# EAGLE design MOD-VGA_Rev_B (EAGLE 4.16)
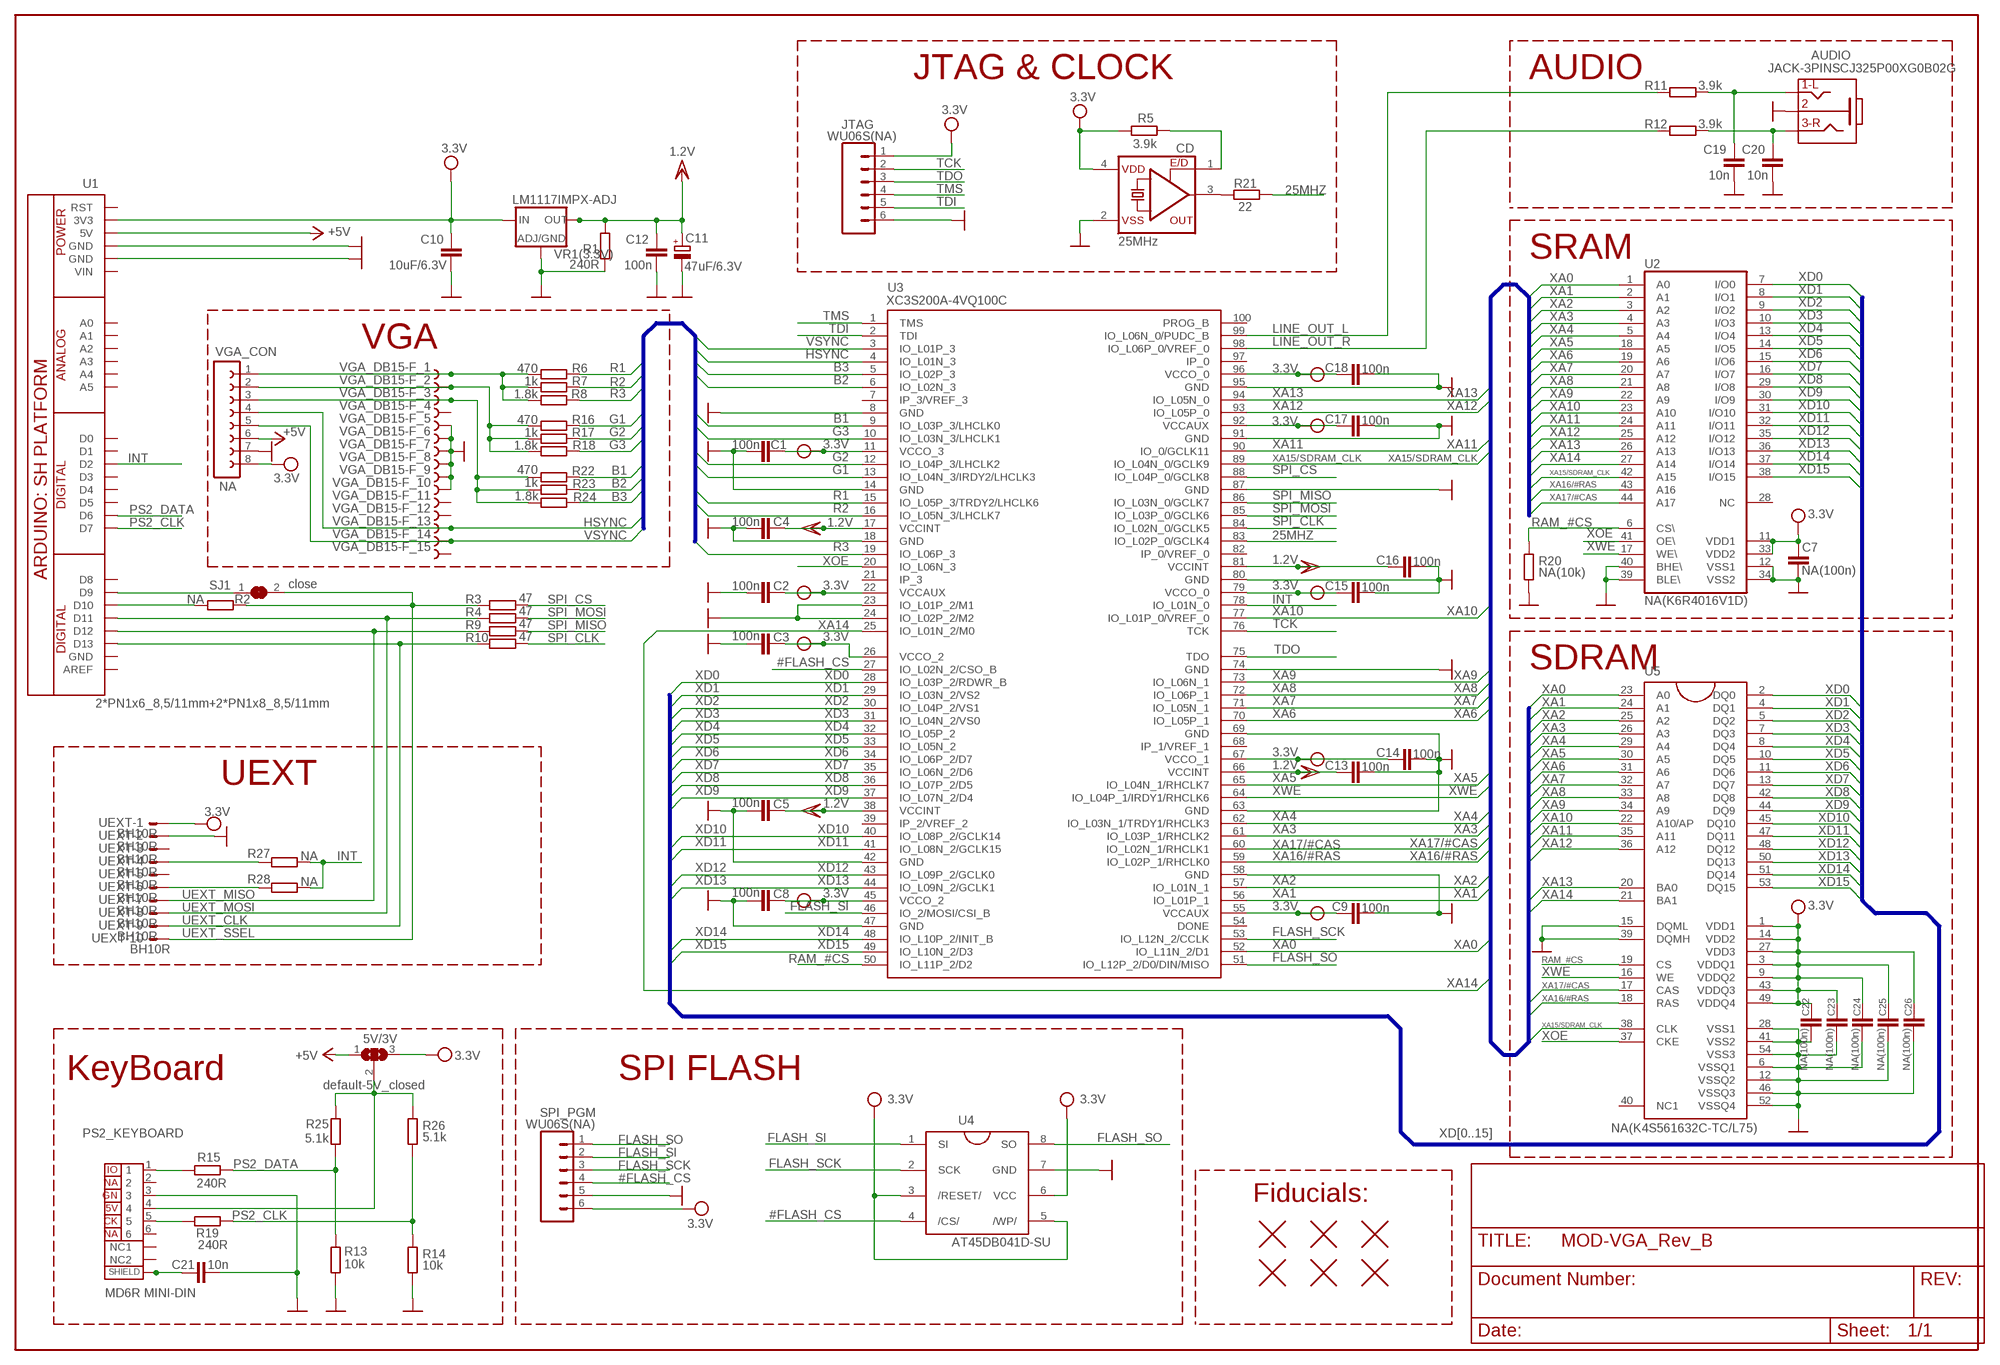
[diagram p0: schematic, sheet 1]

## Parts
5V/3V  default-5V_closed  SJ2W  [SJ_2]
AUDIO  JACK-3PINSCJ325P00XG0B02G  [PHONE_JACK-SMD]
C1  100n  C-EUC0603_5MIL  [C0603_5MIL]
C2  100n  C-EUC0603_5MIL  [C0603_5MIL]
C3  100n  C-EUC0603_5MIL  [C0603_5MIL]
C4  100n  C-EUC0603_5MIL  [C0603_5MIL]
C5  100n  C-EUC0603_5MIL  [C0603_5MIL]
C7  NA(100n)  C-EUC0603MM_NA  [C0603_MM_NA]
C8  100n  C-EUC0603_5MIL  [C0603_5MIL]
C9  100n  C-EUC0603_5MIL  [C0603_5MIL]
C10  10uF/6.3V  C-EUC0603_5MIL  [C0603_5MIL]
C11  47uF/6.3V  CPOL-EUCT3528  [CT3528]
C12  100n  C-EUC0603_5MIL  [C0603_5MIL]
C13  100n  C-EUC0603_5MIL  [C0603_5MIL]
C14  100n  C-EUC0603_5MIL  [C0603_5MIL]
C15  100n  C-EUC0603_5MIL  [C0603_5MIL]
C16  100n  C-EUC0603_5MIL  [C0603_5MIL]
C17  100n  C-EUC0603_5MIL  [C0603_5MIL]
C18  100n  C-EUC0603_5MIL  [C0603_5MIL]
C19  10n  C-EUC0603_5MIL  [C0603_5MIL]
C20  10n  C-EUC0603_5MIL  [C0603_5MIL]
C21  10n  C-EUC0603_5MIL  [C0603_5MIL]
C22  NA(100n)  C-EUC0603MM_NA  [C0603_MM_NA]
C23  NA(100n)  C-EUC0603MM_NA  [C0603_MM_NA]
C24  NA(100n)  C-EUC0603MM_NA  [C0603_MM_NA]
C25  NA(100n)  C-EUC0603MM_NA  [C0603_MM_NA]
C26  NA(100n)  C-EUC0603MM_NA  [C0603_MM_NA]
CD  25MHz  6NC2_CLOCK_DRIVER  [7X5MM_CLOCK_DRIVER]
FID1  FIDUCIAL1X2  [FIDUCIAL-1X2]
FID2  FIDUCIAL1X2  [FIDUCIAL-1X2]
FID3  FIDUCIAL1X2  [FIDUCIAL-1X2]
FID4  FIDUCIAL1X2  [FIDUCIAL-1X2]
FID5  FIDUCIAL1X2  [FIDUCIAL-1X2]
FID6  FIDUCIAL1X2  [FIDUCIAL-1X2]
JTAG  WU06S(NA)  CON61.27MM-6-SMALL  [CON1.27MM-6-SMALL_TRANSITIVE]
PS2_KEYBOARD  MD6R MINI-DIN  PS2PS2  [PS2]
R1  240R  R-EU_R0603_5MIL  [R0603_5MIL]
R2  NA  R-EU_NA  [R0603_NA]
R3  47  R-EU_R0603_5MIL  [R0603_5MIL]
R4  47  R-EU_R0603_5MIL  [R0603_5MIL]
R5  3.9k  R-EU_R0603_5MIL  [R0603_5MIL]
R6  470  R-EU_R0603_5MIL  [R0603_5MIL]
R7  1k  R-EU_R0603_5MIL  [R0603_5MIL]
R8  1.8k  R-EU_R0603_5MIL  [R0603_5MIL]
R9  47  R-EU_R0603_5MIL  [R0603_5MIL]
R10  47  R-EU_R0603_5MIL  [R0603_5MIL]
R11  3.9k  R-EU_R0603_5MIL  [R0603_5MIL]
R12  3.9k  R-EU_R0603_5MIL  [R0603_5MIL]
R13  10k  R-EU_R0603_5MIL  [R0603_5MIL]
R14  10k  R-EU_R0603_5MIL  [R0603_5MIL]
R15  240R  R-EU_R0603_5MIL  [R0603_5MIL]
R16  470  R-EU_R0603_5MIL  [R0603_5MIL]
R17  1k  R-EU_R0603_5MIL  [R0603_5MIL]
R18  1.8k  R-EU_R0603_5MIL  [R0603_5MIL]
R19  240R  R-EU_R0603_5MIL  [R0603_5MIL]
R20  NA(10k)  R-EU_R0603MM_NA  [R0603MM_NA]
R21  22  R-EU_R0603_5MIL  [R0603_5MIL]
R22  470  R-EU_R0603_5MIL  [R0603_5MIL]
R23  1k  R-EU_R0603_5MIL  [R0603_5MIL]
R24  1.8k  R-EU_R0603_5MIL  [R0603_5MIL]
R25  5.1k  R-EU_R0603_5MIL  [R0603_5MIL]
R26  5.1k  R-EU_R0603_5MIL  [R0603_5MIL]
R27  NA  R-EU_R0603_5MIL  [R0603_5MIL]
R28  NA  R-EU_R0603_5MIL  [R0603_5MIL]
SJ1  close  SJSJ-CLOSE  [SJ-CLOSE]
SPI_PGM  WU06S(NA)  CON61.27MM-6-SMALL  [CON1.27MM-6-SMALL_TRANSITIVE]
U1  2*PN1x6_8,5/11mm+2*PN1x8_8,5/11mm  ARDUINO_SH_PLATFORM2  [ARDUINO_MIDI_PLATFORM]
U2  NA(K6R4016V1D)  IDT71V416L  [44TSOP1]
U3  XC3S200A-4VQ100C  XC3S200A  [S-PQFP-G100]
U4  AT45DB041D-SU  AT45DB041B_1  [AT45DB041B_1]
U5  NA(K4S561632C-TC/L75)  K4S561632C-TC/L75  [54TSOPII]
UEXT  BH10R  ML10LE  [ML10L]
VGA_CON  NA  FE08-1  [FE08]
VGA_DB15-F  VGA15  DB1522  [DB15-F_22MM]
VR1(3.3V)  LM1117IMPX-ADJ  LM1117  [SOT223]

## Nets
25MHZ: R21.2 U3.83(IO_L02P_0/GCLK4)
#FLASH_CS: SPI_PGM.4 U3.27(IO_L02N_2/CSO_B) U4.4(/CS/)
+5V: 5V/3V.1 U1.5V VGA_CON.6
B1: R22.2 U3.9(IO_L03P_3/LHCLK0)
B2: R23.2 U3.6(IO_L02N_3)
B3: R24.1 U3.5(IO_L02P_3)
FLASH_SCK: SPI_PGM.3 U3.53(IO_L12N_2/CCLK) U4.2(SCK)
FLASH_SI: SPI_PGM.2 U3.46(IO_2/MOSI/CSI_B) U4.1(SI)
FLASH_SO: SPI_PGM.1 U3.51(IO_L12P_2/D0/DIN/MISO) U4.8(SO)
G1: R16.2 U3.13(IO_L04N_3/IRDY2/LHCLK3)
G2: R17.2 U3.12(IO_L04P_3/LHCLK2)
G3: R18.2 U3.10(IO_L03N_3/LHCLK1)
GND [pwr]: AUDIO.1 C1.2 C2.2 C3.2 C4.2 C5.2 C7.2 C8.2 C9.2 C10.2 C11.- C12.2 C13.2 C14.2 C15.2 C16.2 C17.2 C18.2 C19.2 C20.2 C21.2 C22.2 C23.2 C24.2 C25.2 C26.2 CD.2(VSS) JTAG.6 PS2_KEYBOARD.3 R1.2 R13.2 R14.2 R20.2 SPI_PGM.5 U1.GND U1.GND@1(GND) U2.12(VSS1) U2.34(VSS2) U2.39(BLE\) U2.40(BHE\) U3.8(GND) U3.14(GND) U3.18(GND) U3.23(IO_L01P_2/M1) U3.24(IO_L02P_2/M2) U3.42(GND) U3.47(GND) U3.58(GND) U3.63(GND) U3.69(GND) U3.74(GND) U3.80(GND) U3.87(GND) U3.91(GND) U3.95(GND) U4.7(GND) U5.6(VSSQ1) U5.12(VSSQ2) U5.15(DQML) U5.28(VSS1) U5.39(DQMH) U5.41(VSS2) U5.46(VSSQ3) U5.52(VSSQ4) U5.54(VSS3) UEXT.2 VGA_CON.7 VGA_DB15-F.5 VGA_DB15-F.6 VGA_DB15-F.7 VGA_DB15-F.8 VGA_DB15-F.9 VGA_DB15-F.10 VR1(3.3V).1(ADJ/GND)
HSYNC: U3.4(IO_L01N_3) VGA_CON.4 VGA_DB15-F.13
INT: R27.2 R28.2 U1.D2 U3.78(IO_L01N_0)
LINE_OUT_L: R11.2 U3.99(IO_L06N_0/PUDC_B)
LINE_OUT_R: R12.2 U3.98(IO_L06P_0/VREF_0)
N$1: R2.1 U1.D10
N$2: SJ1.1 U1.D9
N$3: PS2_KEYBOARD.1 R15.1
N$4: PS2_KEYBOARD.5 R19.1
N$5: 5V/3V.2 PS2_KEYBOARD.4 R25.1 R26.1
N$6: CD.1(E/D) R5.1
N$7: R27.1 UEXT.4
N$9: AUDIO.5 C19.1 R11.1
N$10: AUDIO.2 C20.1 R12.1
N$11: CD.3(OUT) R21.1
N$12: R28.1 UEXT.6
N$29: R16.1 R17.1 R18.1 VGA_CON.2 VGA_DB15-F.2
N$37: R6.1 R7.1 R8.1 VGA_CON.1 VGA_DB15-F.1
N$40: R22.1 R23.1 R24.2 VGA_CON.3 VGA_DB15-F.3
N$86: C21.1 PS2_KEYBOARD.SHIELD1 PS2_KEYBOARD.SHIELD2 PS2_KEYBOARD.SHIELD3
PS2_CLK: R14.1 R19.2 R26.2 U1.D7
PS2_DATA: R13.1 R15.2 R25.2 U1.D6
R1: R6.2 U3.15(IO_L05P_3/TRDY2/LHCLK6)
R2: R7.2 U3.16(IO_L05N_3/LHCLK7)
R3: R8.2 U3.19(IO_L06P_3)
RAM_#CS: R20.1 U2.6(CS\) U3.50(IO_L11P_2/D2) U5.19(CS)
SPI_CLK: R10.2 U3.84(IO_L02N_0/GCLK5)
SPI_CS: R3.2 U3.88(IO_L04P_0/GCLK8)
SPI_MISO: R9.2 U3.86(IO_L03N_0/GCLK7)
SPI_MOSI: R4.2 U3.85(IO_L03P_0/GCLK6)
TCK: JTAG.2 U3.76(TCK)
TDI: JTAG.5 U3.2(TDI)
TDO: JTAG.3 U3.75(TDO)
TMS: JTAG.4 U3.1(TMS)
UEXT_CLK: R10.1 U1.D13 UEXT.9
UEXT_MISO: R9.1 U1.D12 UEXT.7
UEXT_MOSI: R4.1 U1.D11 UEXT.8
UEXT_SSEL: R2.2 R3.1 SJ1.2 UEXT.10
VCC [pwr]: 5V/3V.3 C1.1 C2.1 C3.1 C7.1 C8.1 C9.1 C10.1 C14.1 C15.1 C17.1 C18.1 C22.1 C23.1 C24.1 C25.1 C26.1 CD.4(VDD) JTAG.1 R5.2 SPI_PGM.6 U1.3V3 U2.11(VDD1) U2.33(VDD2) U3.11(VCCO_3) U3.22(VCCAUX) U3.26(VCCO_2) U3.45(VCCO_2) U3.55(VCCAUX) U3.67(VCCO_1) U3.79(VCCO_0) U3.92(VCCAUX) U3.96(VCCO_0) U4.3(/RESET/) U4.5(/WP/) U4.6(VCC) U5.1(VDD1) U5.3(VDDQ1) U5.9(VDDQ2) U5.14(VDD2) U5.27(VDD3) U5.43(VDDQ3) U5.49(VDDQ4) UEXT.1 VGA_CON.8 VR1(3.3V).3(IN) ; supply symbol labelled 3.3V
VCC/2: C4.1 C5.1 C11.+ C12.1 C13.1 C16.1 R1.1 U3.17(VCCINT) U3.38(VCCINT) U3.66(VCCINT) U3.81(VCCINT) VR1(3.3V).2(OUT) VR1(3.3V).4(RAD) ; supply symbol labelled 1.2V
VSYNC: U3.3(IO_L01P_3) VGA_CON.5 VGA_DB15-F.14
XA0: U2.1(A0) U3.52(IO_L11N_2/D1) U5.23(A0)
XA1: U2.2(A1) U3.56(IO_L01P_1) U5.24(A1)
XA2: U2.3(A2) U3.57(IO_L01N_1) U5.25(A2)
XA3: U2.4(A3) U3.61(IO_L03P_1/RHCLK2) U5.26(A3)
XA4: U2.5(A4) U3.62(IO_L03N_1/TRDY1/RHCLK3) U5.29(A4)
XA5: U2.18(A5) U3.65(IO_L04N_1/RHCLK7) U5.30(A5)
XA6: U2.19(A6) U3.70(IO_L05P_1) U5.31(A6)
XA7: U2.20(A7) U3.71(IO_L05N_1) U5.32(A7)
XA8: U2.21(A8) U3.72(IO_L06P_1) U5.33(A8)
XA9: U2.22(A9) U3.73(IO_L06N_1) U5.34(A9)
XA10: U2.23(A10) U3.77(IO_L01P_0/VREF_0) U5.22(A10/AP)
XA11: U2.24(A11) U3.90(IO_0/GCLK11) U5.35(A11)
XA12: U2.25(A12) U3.93(IO_L05P_0) U5.36(A12)
XA13: U2.26(A13) U3.94(IO_L05N_0) U5.20(BA0)
XA14: U2.27(A14) U3.25(IO_L01N_2/M0) U5.21(BA1)
XA15/SDRAM_CLK: U2.42(A15) U3.89(IO_L04N_0/GCLK9) U5.38(CLK)
XA16/#RAS: U2.43(A16) U3.59(IO_L02P_1/RHCLK0) U5.18(RAS)
XA17/#CAS: U2.44(A17) U3.60(IO_L02N_1/RHCLK1) U5.17(CAS)
XD0: U2.7(I/O0) U3.28(IO_L03P_2/RDWR_B) U5.2(DQ0)
XD1: U2.8(I/O1) U3.29(IO_L03N_2/VS2) U5.4(DQ1)
XD2: U2.9(I/O2) U3.30(IO_L04P_2/VS1) U5.5(DQ2)
XD3: U2.10(I/O3) U3.31(IO_L04N_2/VS0) U5.7(DQ3)
XD4: U2.13(I/O4) U3.32(IO_L05P_2) U5.8(DQ4)
XD5: U2.14(I/O5) U3.33(IO_L05N_2) U5.10(DQ5)
XD6: U2.15(I/O6) U3.34(IO_L06P_2/D7) U5.11(DQ6)
XD7: U2.16(I/O7) U3.35(IO_L06N_2/D6) U5.13(DQ7)
XD8: U2.29(I/O8) U3.36(IO_L07P_2/D5) U5.42(DQ8)
XD9: U2.30(I/O9) U3.37(IO_L07N_2/D4) U5.44(DQ9)
XD10: U2.31(I/O10) U3.40(IO_L08P_2/GCLK14) U5.45(DQ10)
XD11: U2.32(I/O11) U3.41(IO_L08N_2/GCLK15) U5.47(DQ11)
XD12: U2.35(I/O12) U3.43(IO_L09P_2/GCLK0) U5.48(DQ12)
XD13: U2.36(I/O13) U3.44(IO_L09N_2/GCLK1) U5.50(DQ13)
XD14: U2.37(I/O14) U3.48(IO_L10P_2/INIT_B) U5.51(DQ14)
XD15: U2.38(I/O15) U3.49(IO_L10N_2/D3) U5.53(DQ15)
XOE: U2.41(OE\) U3.20(IO_L06N_3) U5.37(CKE)
XWE: U2.17(WE\) U3.64(IO_L04P_1/IRDY1/RHCLK6) U5.16(WE)
Unconnected: PS2_KEYBOARD.2 PS2_KEYBOARD.6 PS2_KEYBOARD.NC1 PS2_KEYBOARD.NC2 U1.A0 U1.A1 U1.A2 U1.A3 U1.A4 U1.A5 U1.AREF U1.D0 U1.D1 U1.D3 U1.D4 U1.D5 U1.D8 U1.GND@2(GND) U1.RST U1.VIN U2.28(NC) U3.7(IP_3/VREF_3) U3.21(IP_3) U3.39(IP_2/VREF_2) U3.54(DONE) U3.68(IP_1/VREF_1) U3.82(IP_0/VREF_0) U3.97(IP_0) U3.100(PROG_B) U5.40(NC1) UEXT.3 UEXT.5 VGA_DB15-F.4 VGA_DB15-F.11 VGA_DB15-F.12 VGA_DB15-F.15

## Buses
XA[0..14],XA15/SDRAM_CLK,XA16/#RAS,XA17/#CAS
XD[0..15]
R[1..3],G[1..3],B[1..3],HSYNC,VSYNC

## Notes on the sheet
- JTAG & CLOCK | AUDIO
- SRAM
- VGA
- SDRAM
- UEXT
- KeyBoard | SPI FLASH
- Fiducials:

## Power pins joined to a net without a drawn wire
GND: VGA_DB15-F.GND1 VGA_DB15-F.GND2

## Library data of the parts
5V/3V = jumper:SJ2W: SMD solder JUMPER
AUDIO = gogo:JACK-3PIN
C1-C5 C7-C10 C12-C26 = rcl:C-EU: CAPACITOR, European symbol
C11 = rcl:CPOL-EU: POLARIZED CAPACITOR, European symbol
CD = gogo:6NC2_CLOCK_DRIVER
FID1-FID6 = SparkFunEagle-6-6-07:FIDUCIAL: Fiducial Alignment Points
JTAG SPI_PGM = DOUBLE-SIDE:CON6: CONNECTORS - 6 PINS
PS2_KEYBOARD = OLIMEX_CONNECTORS:PS2
R1-R28 = rcl:R-EU_: RESISTOR, European symbol
SJ1 = jumper:SJ: SMD solder JUMPER
U1 = OLIMEX_CASES:ARDUINO_SH_PLATFORM
U2 = gogo:IDT71V416L
U3 = OLIMEX_IC:XC3S200A
U4 = IP4w:AT45DB041B_1
U5 = SIRRUS:K4S561632C-TC/L75
UEXT = con-harting-ml:ML10?E: HARTING
VGA_CON = con-lsta:FE08-1: FEMALE HEADER
VGA_DB15-F = OLIMEX_CONNECTORS:DB15
VR1(3.3V) = arm:LM1117

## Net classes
1 pwr: width 0.203 mm

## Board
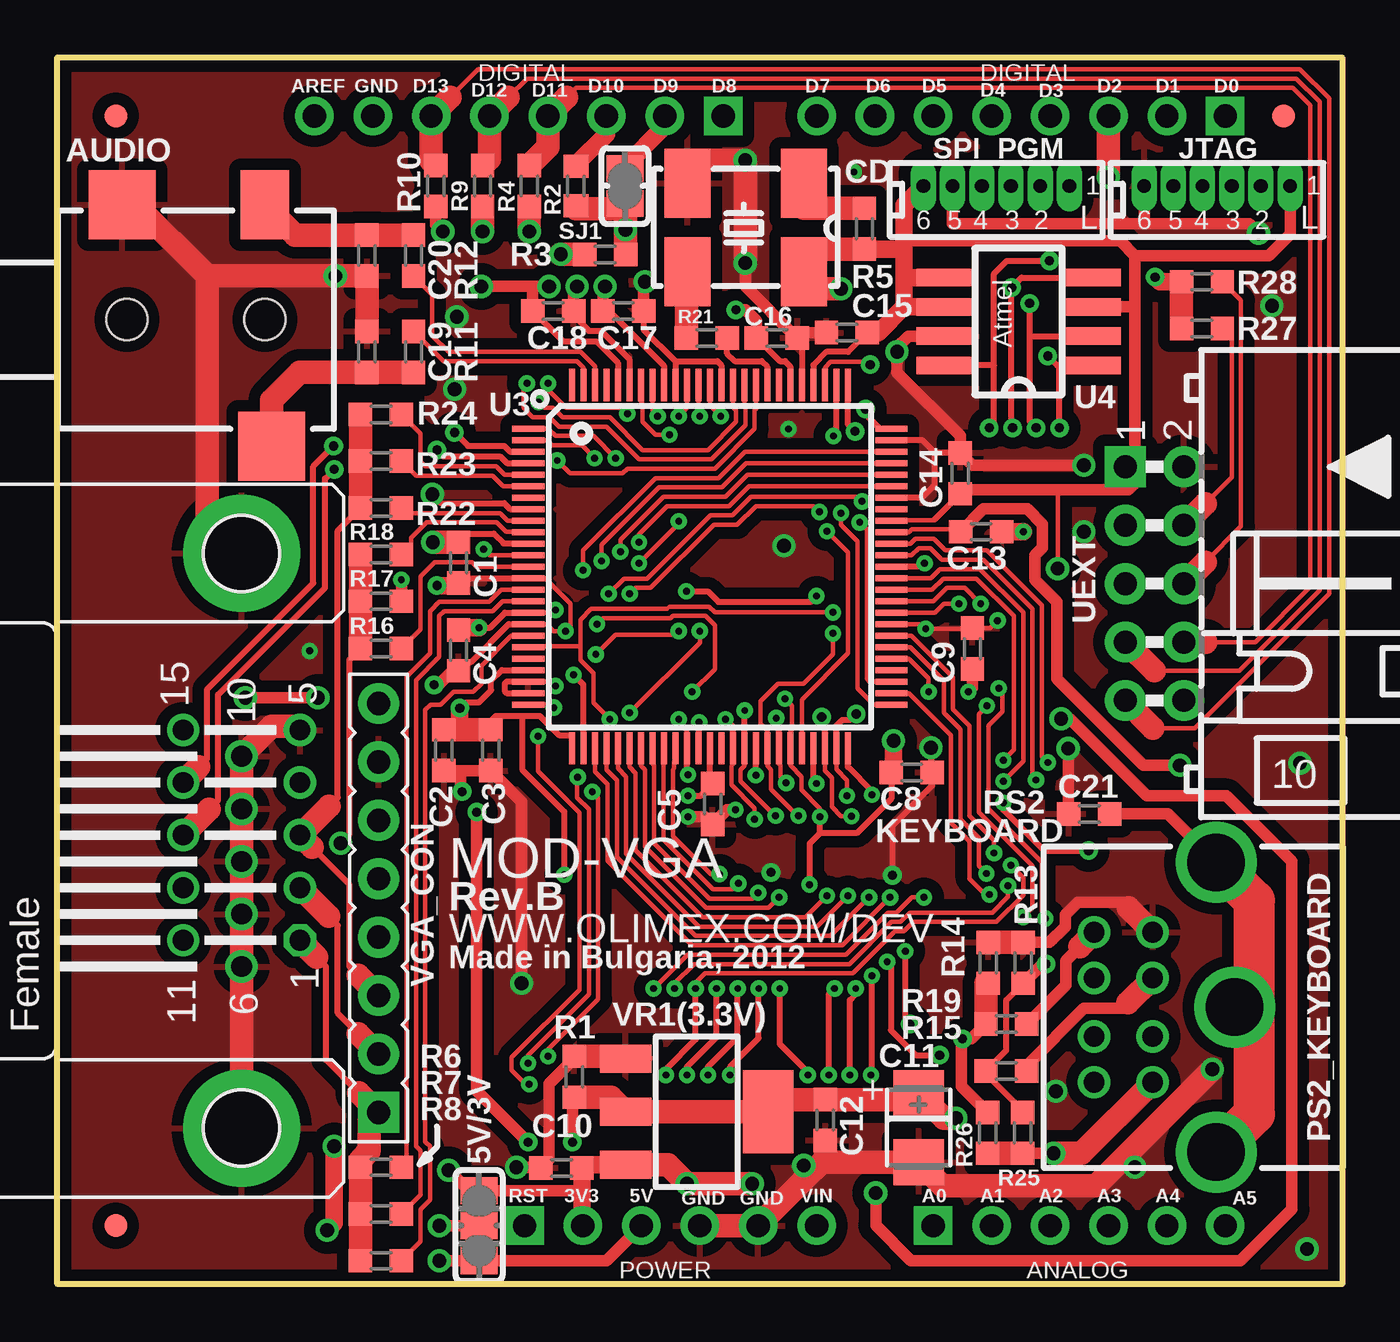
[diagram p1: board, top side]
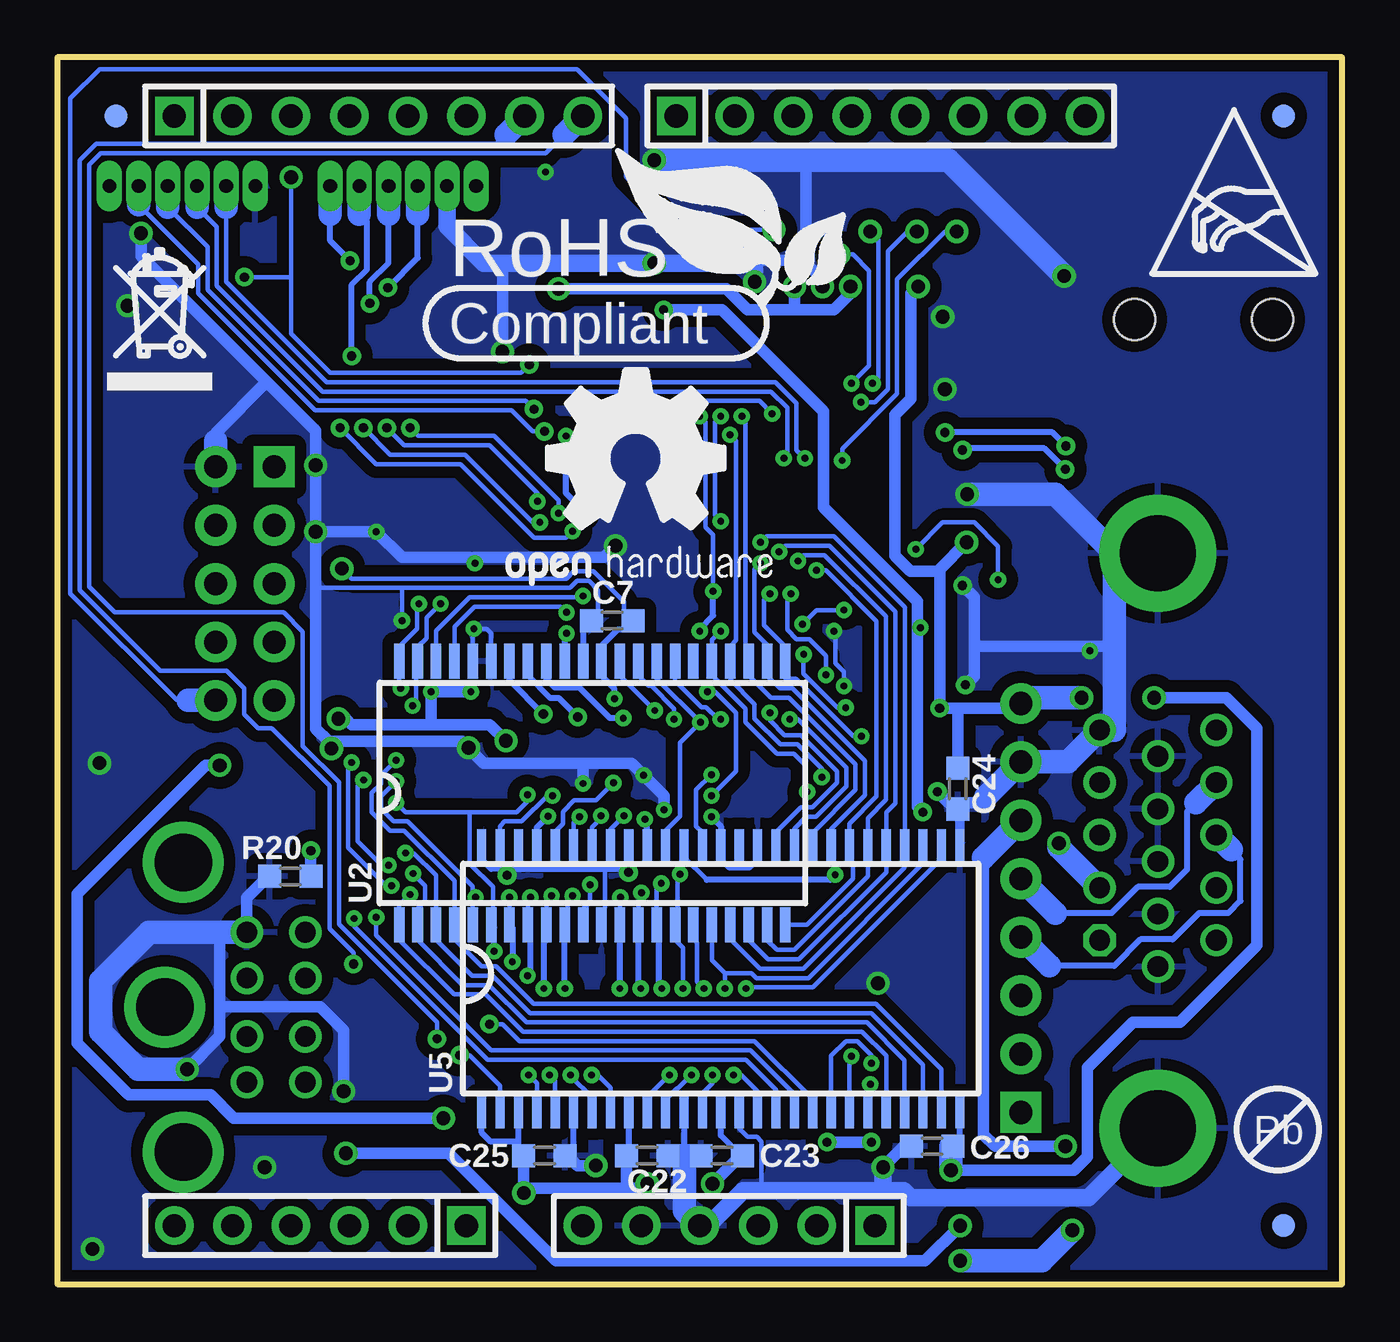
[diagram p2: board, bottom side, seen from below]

Size 55.88 x 53.34 mm. Coordinates in mm from the lower left corner, seen from the top.
Copper layers (1+16): Top 0.035mm / dielectric 1.5mm / Bottom 0.035mm
Design rules "default": minimum track width 8mil, minimum drill 11mil, track to track 7.5mil, track to pad 7.5mil, pad to pad 7.5mil, via to via 7.5mil, smd to smd 1mil, copper to edge 10mil, drill to drill 8mil, minimum pad ring 10mil, minimum via ring 8mil, stop-mask expansion 4mil, vias tented up to drill 25mil, thermal gap 20mil

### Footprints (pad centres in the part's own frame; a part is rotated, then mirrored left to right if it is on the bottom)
SJ_2 = smd 1.168 x 1.6: 1 -1.524,0; 2 0,0; 3 1.524,0
PHONE_JACK-SMD = smd 2.9 x 3: 1 -0.2,5; 5 6.3,-5.5 | smd 2.1 x 3: 2 6,5 | hole 1.8: 0,0; 6,0
C0603_5MIL = smd 1.016 x 1.016: 1 -0.889,0; 2 0.889,0
C0603_MM_NA = smd 1 x 1: 1 -0.9,0; 2 0.9,0
CT3528 = smd 2 x 2.2: + -1.5,0; - 1.5,0
7X5MM_CLOCK_DRIVER = smd 2 x 3: 1 -2.54,-1.941; 2 2.54,-1.941; 3 2.54,1.901; 4 -2.54,1.901
FIDUCIAL-1X2 = smd 1 x 1: 1 0,0
CON1.27MM-6-SMALL_TRANSITIVE = drill 0.6 pad 1.016 long: 1 3.175,0; 2 1.905,0; 3 0.635,0; 4 -0.635,0; 5 -1.905,0; 6 -3.175,0
PS2 = drill 0.9 round: 1 1.27,1.77; 2 -1.27,1.77; 3 3.26,1.77; 4 -3.26,1.77; 5 3.26,4.31; 6 -3.26,4.31; NC1 -1.27,4.31; NC2 1.27,4.31 | drill 2.5 round: SHIELD1 -6.3,-1; SHIELD2 0,-1.8; SHIELD3 6.3,-1
R0603_5MIL = smd 1.016 x 1.016: 1 -0.889,0; 2 0.889,0
R0603_NA = smd 1 x 1.1: 1 -0.85,0; 2 0.85,0
R0603MM_NA = smd 1 x 1: 1 -0.9,0; 2 0.9,0
SJ-CLOSE = smd 1.168 x 1.6: 1 -0.762,0; 2 0.762,0
ARDUINO_MIDI_PLATFORM = drill 1.016 pad 1.676 round: 3V3 22.86,2.54; 5V 25.4,2.54; A1 40.64,2.54; A2 43.18,2.54; A3 45.72,2.54; A4 48.26,2.54; A5 50.8,2.54; AREF 11.176,50.8; D1 48.26,50.8; D2 45.72,50.8; D3 43.18,50.8; D4 40.64,50.8; D5 38.1,50.8; D6 35.56,50.8; D7 33.02,50.8; D9 26.416,50.8; D10 23.876,50.8; D11 21.336,50.8; D12 18.796,50.8; D13 16.256,50.8; GND 27.94,2.54; GND@1 30.48,2.54; GND@2 13.716,50.8; VIN 33.02,2.54 | drill 1.016 pad 1.676 square: A0 38.1,2.54; D0 50.8,50.8; D8 28.956,50.8; RST 20.32,2.54
44TSOP1 = smd 0.457 x 1.524: 1 -8.468,-5.74; 2 -7.668,-5.74; 3 -6.867,-5.74; 4 -6.067,-5.74; 5 -5.267,-5.74; 6 -4.467,-5.74; 7 -3.667,-5.74; 8 -2.867,-5.74; 9 -2.067,-5.74; 10 -1.267,-5.74; 11 -0.467,-5.74; 12 0.333,-5.74; 13 1.134,-5.74; 14 1.934,-5.74; 15 2.734,-5.74; 16 3.534,-5.74; 17 4.334,-5.74; 18 5.134,-5.74; 19 5.934,-5.74; 20 6.734,-5.74; 21 7.534,-5.74; 22 8.335,-5.74; 23 8.335,5.715; 24 7.534,5.715; 25 6.734,5.715; 26 5.934,5.715; 27 5.134,5.715; 28 4.334,5.715; 29 3.534,5.715; 30 2.734,5.715; 31 1.934,5.715; 32 1.134,5.715; 33 0.334,5.715; 34 -0.466,5.715; 35 -1.267,5.715; 36 -2.067,5.715; 37 -2.867,5.715; 38 -3.667,5.715; 39 -4.467,5.715; 40 -5.267,5.715; 41 -6.067,5.715; 42 -6.867,5.715; 43 -7.668,5.715; 44 -8.468,5.715
S-PQFP-G100 = smd 1.4 x 0.254: 1 -7.9,6; 2 -7.9,5.5; 3 -7.9,5; 4 -7.9,4.5; 5 -7.9,4; 6 -7.9,3.5; 7 -7.9,3; 8 -7.9,2.5; 9 -7.9,2; 10 -7.9,1.5; 11 -7.9,1; 12 -7.9,0.5; 13 -7.9,0; 14 -7.9,-0.5; 15 -7.9,-1; 16 -7.9,-1.5; 17 -7.9,-2; 18 -7.9,-2.5; 19 -7.9,-3; 20 -7.9,-3.5; 21 -7.9,-4; 22 -7.9,-4.5; 23 -7.9,-5; 24 -7.9,-5.5; 25 -7.9,-6; 51 7.9,-6; 52 7.9,-5.5; 53 7.9,-5; 54 7.9,-4.5; 55 7.9,-4; 56 7.9,-3.5; 57 7.9,-3; 58 7.9,-2.5; 59 7.9,-2; 60 7.9,-1.5; 61 7.9,-1; 62 7.9,-0.5; 63 7.9,0; 64 7.9,0.5; 65 7.9,1; 66 7.9,1.5; 67 7.9,2; 68 7.9,2.5; 69 7.9,3; 70 7.9,3.5; 71 7.9,4; 72 7.9,4.5; 73 7.9,5; 74 7.9,5.5; 75 7.9,6 | smd 0.254 x 1.4: 26 -6,-7.9; 27 -5.5,-7.9; 28 -5,-7.9; 29 -4.5,-7.9; 30 -4,-7.9; 31 -3.5,-7.9; 32 -3,-7.9; 33 -2.5,-7.9; 34 -2,-7.9; 35 -1.5,-7.9; 36 -1,-7.9; 37 -0.5,-7.9; 38 0,-7.9; 39 0.5,-7.9; 40 1,-7.9; 41 1.5,-7.9; 42 2,-7.9; 43 2.5,-7.9; 44 3,-7.9; 45 3.5,-7.9; 46 4,-7.9; 47 4.5,-7.9; 48 5,-7.9; 49 5.5,-7.9; 50 6,-7.9; 76 6,7.9; 77 5.5,7.9; 78 5,7.9; 79 4.5,7.9; 80 4,7.9; 81 3.5,7.9; 82 3,7.9; 83 2.5,7.9; 84 2,7.9; 85 1.5,7.9; 86 1,7.9; 87 0.5,7.9; 88 0,7.9; 89 -0.5,7.9; 90 -1,7.9; 91 -1.5,7.9; 92 -2,7.9; 93 -2.5,7.9; 94 -3,7.9; 95 -3.5,7.9; 96 -4,7.9; 97 -4.5,7.9; 98 -5,7.9; 99 -5.5,7.9; 100 -6,7.9
AT45DB041B_1 = smd 0.762 x 2.54: 1 -1.905,-3.175; 2 -0.635,-3.175; 3 0.635,-3.175; 4 1.905,-3.175; 5 1.905,3.175; 6 0.635,3.175; 7 -0.635,3.175; 8 -1.905,3.175
54TSOPII = smd 0.4 x 1.4: 1 -10.4,-6; 2 -9.6,-6; 3 -8.8,-6; 4 -8,-6; 5 -7.2,-6; 6 -6.4,-6; 7 -5.6,-6; 8 -4.8,-6; 9 -4,-6; 10 -3.2,-6; 11 -2.4,-6; 12 -1.6,-6; 13 -0.8,-6; 14 0,-6; 15 0.8,-6; 16 1.6,-6; 17 2.4,-6; 18 3.2,-6; 19 4,-6; 20 4.8,-6; 21 5.6,-6; 22 6.4,-6; 23 7.2,-6; 24 8,-6; 25 8.8,-6; 26 9.6,-6; 27 10.4,-6; 28 10.4,5.6; 29 9.6,5.6; 30 8.8,5.6; 31 8,5.6; 32 7.2,5.6; 33 6.4,5.6; 34 5.6,5.6; 35 4.8,5.6; 36 4,5.6; 37 3.2,5.6; 38 2.4,5.6; 39 1.6,5.6; 40 0.8,5.6; 41 0,5.6; 42 -0.8,5.6; 43 -1.6,5.6; 44 -2.4,5.6; 45 -3.2,5.6; 46 -4,5.6; 47 -4.8,5.6; 48 -5.6,5.6; 49 -6.4,5.6; 50 -7.2,5.6; 51 -8,5.6; 52 -8.8,5.6; 53 -9.6,5.6; 54 -10.4,5.6
ML10L = drill 1 pad 1.778 square: 1 -5.08,-1.27 | drill 1 pad 1.778 round: 2 -5.08,1.27; 3 -2.54,-1.27; 4 -2.54,1.27; 5 0,-1.27; 6 0,1.27; 7 2.54,-1.27; 8 2.54,1.27; 9 5.08,-1.27; 10 5.08,1.27
FE08 = drill 1.016 pad 1.778 square: 1 -8.89,0 | drill 1.016 pad 1.778 round: 2 -6.35,0; 3 -3.81,0; 4 -1.27,0; 5 1.27,0; 6 3.81,0; 7 6.35,0; 8 8.89,0
DB15-F_22MM = drill 0.9 octagon: 1 4.329,6.35 | drill 0.9 round: 2 2.043,6.35; 3 -0.243,6.35; 4 -2.529,6.35; 5 -4.815,6.35; 6 5.472,3.81; 7 3.186,3.81; 8 0.9,3.81; 9 -1.386,3.81; 10 -3.672,3.81; 11 4.329,1.27; 12 2.043,1.27; 13 -0.243,1.27; 14 -2.529,1.27; 15 -4.815,1.27 | drill 3.302 pad 5.08 round: GND1 -12.497,3.81; GND2 12.497,3.81
SOT223 = smd 1.219 x 2.235: 1 -2.311,-3.099; 2 0,-3.099; 3 2.311,-3.099 | smd 3.6 x 2.2: 4 0,3.099

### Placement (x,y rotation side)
5V/3V  18.34,2.54 90 top
AUDIO  3.02,41.94 0 top
C1  17.45,31.37 270 top
C2  16.81,23.22 270 top
C3  18.85,23.22 270 top
C4  17.45,27.56 270 top
C5  28.5,20.88 270 top
C7  31.75,28.85 180 bottom
C8  37.16,22.25 0 top
C9  39.8,27.64 90 top
C10  21.92,5.05 180 top
C11  37.47,6.81 270 top
C12  33.4,7.14 270 top
C13  40.18,32.72 0 top
C14  39.27,35.26 90 top
C15  34.34,41.38 180 top
C16  31.29,41.15 0 top
C17  24.61,42.32 0 top
C18  21.56,42.32 0 top
C19  13.46,40.54 90 top
C20  13.46,44.73 270 top
C21  44.88,20.45 180 top
C22  30.23,5.59 0 bottom
C23  26.97,5.59 180 bottom
C24  16.71,21.54 270 bottom
C25  34.7,5.59 0 bottom
C26  17.83,5.99 180 bottom
CD  29.94,45.93 180 top
FID1  2.54,2.54 0 top
FID2  53.34,50.8 0 top
FID3  2.54,50.8 0 top
FID4  2.54,2.54 0 bottom
FID5  2.54,50.8 0 bottom
FID6  53.34,50.8 0 bottom
JTAG  50.44,47.75 0 top
PS2_KEYBOARD  49.41,12.04 90 top
R1  22.48,9.02 90 top
R2  22.56,47.75 270 top
R3  23.83,44.78 180 top
R4  20.52,47.75 270 top
R5  35.1,45.9 270 top
R6  14.07,5.08 0 top
R7  14.07,3.05 0 top
R8  14.07,1.02 0 top
R9  18.49,47.75 270 top
R10  16.46,47.75 270 top
R11  15.49,40.54 90 top
R12  15.49,44.73 270 top
R13  42.01,13.97 90 top
R14  40.49,13.97 90 top
R15  41.27,9.27 180 top
R16  14.07,27.64 0 top
R17  14.07,29.69 0 top
R18  14.07,31.72 0 top
R19  41.27,11.3 180 top
R20  45.75,17.73 180 bottom
R21  28.24,41.15 0 top
R22  14.07,33.76 0 top
R23  14.07,35.79 0 top
R24  14.07,37.82 180 top
R25  41.99,6.58 90 top
R26  40.46,6.58 90 top
R27  49.78,41.55 180 top
R28  49.78,43.59 180 top
SJ1  24.69,47.75 270 top
SPI_PGM  40.84,47.75 0 top
U1  0,0 0 top
U2  32.55,21.37 0 bottom
U3  28.38,31.2 0 top
U4  41.81,41.86 90 top
U5  27.03,13.49 0 bottom
U$1  [RECYCLE_BIN1/8]  53.72,38.86 0 bottom
U$2  [ROHS]  38.86,40.89 0 bottom
U$3  [ESD_SYMBOL]  8.26,43.94 0 bottom
U$4  [PB_SMALL]  2.79,6.73 0 bottom
U$5  [LOGO-OPENHARDWARE_8X8]  30.73,35.81 0 bottom
UEXT  47.73,30.46 270 top
VGA_CON  13.97,16.36 90 top
VGA_DB15-F  4.2,19.28 270 top
VR1(3.3V)  27.81,7.49 270 top

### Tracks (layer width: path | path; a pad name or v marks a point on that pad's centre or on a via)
25MHZ
  Top 0.254: U3.83 30.88,39.88 30.63,40.13 29.46,40.13 29.13,40.46 R21.2
#FLASH_CS  (via drill 0.3, 0.4)
  Top 0.203: v23.98,30.02 24.64,30.68 25.65,30.68 28.4,33.43 29.36,33.43 30.18,34.24 34.8,34.24 v35,34.04
  Top 0.254: U3.27 22.88,26.07 v22.45,26.49 | U4.4 41.94,43.76 v41.5,43.33 41.5,37.29 v41.55,37.24
  Bottom 0.203: v22.45,26.49 22.45,27.33 23.16,28.04 23.72,28.04 24.13,28.45 24.13,29.87 v23.98,30.02 | v35,34.04 35,34.39 37.08,36.47 40.79,36.47 v41.55,37.24
  Bottom 0.254: v41.5,43.33 40.21,44.63 40.21,46.53
  Bottom 1.016: 40.21,46.53 SPI_PGM.4
+5V  (via drill 0.6 pad 0.61)
  Top 0.508: v16.61,1.02 5V/3V.1 23.88,1.02 U1.5V
  Top 0.762: v11.73,2.34 12.04,2.64 v12.04,5.99
  Bottom 0.508: v12.04,5.99 15.09,5.99 15.6,6.5 15.6,18.54
  Bottom 1.016: v16.61,1.02 13.06,1.02 v11.73,2.34 | 15.6,18.54 VGA_CON.6
B1
  Top 0.203: U3.9 19.59,33.2 19.25,33.53 15.19,33.53 R22.2
B2
  Top 0.203: U3.6 19.38,34.7 18.92,35.15 15.6,35.15 R23.2
B3
  Top 0.203: R24.1 15.8,36.98 15.8,35.76 16,35.56 19.07,35.56 19.44,35.2 U3.5
FLASH_SCK  (via drill 0.3, 0.4)
  Top 0.203: U3.53 35.32,26.2 35.2,26.31 35.2,32.82 v34.9,33.12
  Top 0.254: 42.29,41.22 U4.2 | v42.57,37.24 42.29,37.52 42.29,41.22 | 42.29,41.22 v42.29,42.65
  Bottom 0.203: v34.9,33.12 35.2,33.12 38.15,36.07 41.4,36.07 v42.57,37.24
  Bottom 0.254: 41.48,46.53 41.48,44.4 42.29,43.59 v42.29,42.65
  Bottom 1.016: 41.48,46.53 SPI_PGM.3
FLASH_SI  (via drill 0.3, 0.4)
  Top 0.203: U3.46 32.38,25.42 34.39,27.43 34.39,31.83 v33.48,32.74
  Top 0.254: 43.59,39.95 U4.1 | v43.59,37.24 43.59,39.95 | 43.59,39.95 43.48,39.95 v43.08,40.36
  Bottom 0.203: v33.48,32.74 33.76,32.46 35.15,32.46 38.35,35.66 42.01,35.66 v43.59,37.24 | 42.42,46.2 42.75,46.53
  Bottom 0.254: 42.42,46.2 42.42,44.12 43.08,43.46 v43.08,40.36
  Bottom 1.016: 42.75,46.53 SPI_PGM.2
FLASH_SO  (via drill 0.3, 0.4)
  Top 0.203: U3.51 35.51,25.2 34.8,25.91 34.8,32.31 34.09,33.02 v34.09,33.53
  Top 0.254: 40.74,39.95 U4.8 | 40.74,39.95 40.74,43.94 41.3,44.5 v43.16,44.5 | v40.54,37.24 40.74,37.44 40.74,39.95
  Bottom 0.203: v34.09,33.53 34.09,34.09 36.88,36.88 40.18,36.88 v40.54,37.24
  Bottom 0.254: v43.16,44.5 44.02,45.36 44.02,46.53
  Bottom 1.016: 44.02,46.53 SPI_PGM.1
G1
  Top 0.203: 14.99,27.64 R16.2 15.8,28.47 15.8,30.79 16.41,31.39 18.03,31.39 18.23,31.2 U3.13
G2  (via drill 0.3 pad 0.61)
  Top 0.203: U3.12 18.8,31.7 v18.54,31.95
  Top 0.508: R17.2 v14.96,30.63
  Bottom 0.203: v18.54,31.95 17.37,33.12 16,33.12 14.96,32.08 v14.96,30.63
G3
  Top 0.203: U3.10 20.46,32.72 19.51,32.72 19.1,33.12 16.05,33.12 15.39,32.46 15.39,32.16 R18.2
GND  (via drill 0.3, 0.4, 0.6, 0.6 pad 0.61)
  Top 0.203: U3.42 | U3.14 21.22,30.7 22.33,29.59 22.33,28.63 v22.1,28.4 21.59,28.4 21.29,28.7 U3.18 | U3.58 37.57,28.7 v37.77,28.5 39.78,28.5 C9.2 40.56,28.52 v40.89,28.85 | 38.15,36.14 38.15,36.17 | U3.23 21.48,26.2 v21.67,26.01
  Top 0.254: U3.14 17.77,30.7 17.45,30.38 C1.2 | U3.63 37.57,31.2 v37.72,31.34 | v30.38,22.12 U3.42 | U3.18 19.63,28.7 17.98,27.05 17.83,27.05 C4.2 | U3.47 32.88,21.91 v33.02,21.77 | U3.69 37.6,34.2 38.15,34.75 38.15,36.14 C14.2 | U3.74 37.62,36.7 38.15,36.17 | U3.95 24.88,40.22 23.65,41.45 23.11,41.45 22.45,42.11 C18.2 | U3.87 28.88,39.95 28.7,40.13 26.88,40.13 | 26.88,40.13 U3.91 | U3.80 32.38,40.95 C16.2 | v36.32,17.78 36.32,19.94 38.05,21.67 C8.2 38,22.3 v38,23.32 | 26.88,40.13 25.5,41.51 C17.2 | v16.31,34.34 16.69,33.96 19.43,33.96 19.7,33.7 U3.8 | U3.24 19.54,25.7 19.46,25.78 19.46,26.11 19.54,26.2 U3.23
  Top 0.508: R1.2 22.48,9.8 21.39,8.71 21.39,5.41 C10.2 21.01,5.08 v19.96,5.08 | v16.38,26.06 16.59,26.06 17.2,26.67 C4.2 | v27.43,20.32 28.17,20.32 C5.2 29.13,20.62 v29.49,20.62 | C15.2 32.41,41.38 C16.2 32.16,41.15 29.92,43.38 v29.92,44.4 | C18.2 22.45,43.23 v22.61,43.38 | C17.2 25.5,43.54 v25.55,43.59 | 17.53,22.33 C3.2 20.19,20.98 v20.19,13.08 | 17.53,22.33 C2.2 | v17.6,21.41 17.53,21.49 17.53,22.33 | SPI_PGM.5 38.94,46.1 47.27,46.1 | U4.7 37.01,41.22 36.52,40.74 v36.52,40.54 36.52,39.62 39.27,36.88 C14.2 39.8,35.61 v44.65,35.61 | 47.27,46.1 51.84,46.1 v52.25,45.7 | 47.27,46.1 JTAG.6 | R13.2 43.16,14.86 43.84,15.54 43.84,16.05 44.4,16.61 46.33,16.61 46.58,16.36 | PS2_KEYBOARD.3 | v43.97,23.29 43.97,20.47 C21.2 | 32.46,4.52 v32.46,5.16
  Top 0.762: v42.01,32.72 C13.2 | v16.51,30.38 17.45,30.38
  Top 1.016: VR1(3.3V).1 24.61,9.91 R1.2 | VGA_DB15-F.5 10.39,24.26 9.31,24.26 VGA_DB15-F.10 VGA_DB15-F.9 VGA_DB15-F.8 VGA_DB15-F.7 VGA_DB15-F.6 VGA_DB15-F.GND2 | R13.2 R14.2 | C19.2 C20.2 v12.09,43.84 6.5,43.84 | CD.2 27.4,48.87 v29.92,48.87 v29.92,44.4 | VGA_DB15-F.GND1 7.37,31.78 6.5,32.64 6.5,43.84 | PS2_KEYBOARD.3 46.58,16.36 | 33.4,5.31 33.25,5.31 32.46,4.52 U1.GND@1 U1.GND | v50.24,9.35 45.16,4.27 38.51,4.27 C11.- 33.4,5.31 | 33.4,5.31 C12.2 | AUDIO.1 3.4,46.94 6.5,43.84
  Bottom 0.203: U5.41 27.03,18.44 26.67,18.09 25.78,18.09 25.43,18.44 U5.39 | U5.15 26.23,6.77 25.86,6.4 25.45,6.4 25.25,6.2 25.25,4.06 | U2.39 37.01,28.3 37.21,28.5 v37.77,28.5 37.81,28.45 U2.40 | 32.74,28.85 C7.2 32.56,28.85 32.36,29.06 32.36,30.18 32.77,30.58 33.27,30.58 33.58,30.28 40.89,30.28 | 16.63,20.44 16.71,20.52 C24.2 | 40.89,30.28 v40.89,28.85 | 44.65,30.28 40.89,30.28 | v31.04,17.91 31.03,17.92 | 32.05,18.06 32.05,16.36 32.21,16.2 U2.12 | v22.1,28.4 22.05,28.35 22.05,27 21.67,26.62 v21.67,26.01
  Bottom 0.254: U5.52 35.83,18.07 35.81,18.06 | U5.54 37.43,18.48 37.01,18.06 36.32,18.06 | U5.41 27.03,19.91 v27.43,20.32 | C25.2 33.68,5.59 33.43,5.84 U5.6 | U5.12 28.6,7.46 28.6,5.59 | C23.2 27.94,5.59 | 36.32,18.06 35.81,18.06 | v36.32,17.78 36.32,18.06 | U2.34 33.01,28.58 32.74,28.85 | 31.03,17.92 U5.46 | v31.04,17.91 31.19,18.06 32.05,18.06 35.81,18.06
  Bottom 0.406: 16.63,20.44 U5.28
  Bottom 0.508: v29.49,20.62 29.49,21.23 v30.38,22.12 30.91,22.66 33.02,22.66 | 33.02,22.66 v33.02,21.77 | 33.02,22.66 37.34,22.66 v38,23.32 38.28,23.6 43.97,23.6 | v22.61,43.38 22.61,43.69 23.32,44.4 23.32,44.53 | 16.71,20.93 C24.2 | v17.6,21.41 17.12,20.93 16.71,20.93 | 15.49,21.18 15.75,20.93 16.71,20.93 | 23.32,48.87 23.32,44.53 | 23.32,44.53 25.55,44.53 25.55,44.4 | 36.52,44.4 v36.52,40.54 | v16.38,26.06 16,26.44 16,27.74 | v52.25,45.7 52.25,44.7 46.77,39.23 | 46.77,39.23 44.65,37.11 v44.65,35.61 v44.65,32.72 | v44.65,32.72 v42.01,32.72 40.89,31.6 37.97,31.6 v37.72,31.34 37.74,31.34 37.74,31.6 32.11,31.6 v31.6,32.11 | v44.65,32.72 44.65,30.28 44.65,24.16 44.09,23.6 43.97,23.6 | 16,27.74 16,29.87 v16.51,30.38 | 43.97,23.6 v43.97,23.29 | C26.2 19.05,5.99 v19.96,5.08 | 33.68,5.59 33.25,5.16 v32.46,5.16 | v50.24,9.35 48.82,10.77 48.82,12.06 | 48.82,12.06 48.82,15.29 | 9.91,27.74 16,27.74 | R20.2 46.71,17.73 47.64,16.8 PS2_KEYBOARD.3 | v43.43,8.38 43.43,11.05 44.45,12.06 48.82,12.06 | 46.77,39.23 49,37.01 49,36.65
  Bottom 0.762: SPI_PGM.5 38.94,46 37.34,44.4 36.52,44.4 v29.92,44.4 25.55,44.4 v25.55,43.59 | U1.GND 27.58,2.54 26.06,4.06 25.25,4.06 19.96,4.06 | 19.96,4.06 19.05,4.06 18.75,3.76 11.03,3.76 VGA_DB15-F.GND2 | 19.96,4.06 v19.96,5.08
  Bottom 1.016: 15.49,21.18 VGA_CON.7 11.94,22.71 VGA_DB15-F.5 9.91,24.09 9.91,27.74 9.91,31.78 | v12.09,43.84 17.12,48.87 23.32,48.87 v29.92,48.87 | 49,36.65 UEXT.2 | U1.GND 28.6,3.2 28.6,5.59 | 28.6,5.59 C23.2 | 28.6,5.59 C22.2 | PS2_KEYBOARD.3 48.82,15.29 51.89,15.29 54,13.18 54,10.97 52.38,9.35 v50.24,9.35 | 9.91,31.78 VGA_DB15-F.GND1 | 9.91,31.78 12.47,34.34 v16.31,34.34
  other vias: 46.86,5.08 54.05,22.66 17.27,38.91 17.37,42.06 54.36,1.52 52.83,42.55 34.65,48.36 31.8,37.19 10.97,27.53
  pour Bottom (isolate 0.508): -5.08,58.42 -5.08,-5.08 60.96,-5.08 60.96,58.42
  pour Top (isolate 0.508): -2.54,-2.54 58.42,-2.54 58.42,55.88 -2.54,55.88
HSYNC  (via drill 0.4)
  Top 0.254: U3.4 19.55,35.7 19.25,35.99 16.79,35.99 v16.51,36.27 | 6.6,20.66 6.99,21.04 6.99,25.63 11.63,30.28 11.63,35.03 v12.04,35.43
  Top 1.016: VGA_DB15-F.13 6.6,20.66
  Bottom 0.254: 12.72,13.84 9.91,13.84 8.76,14.99 7.37,14.99 6.22,16.13 4.95,16.13 4.42,16.66 4.42,18.47 4.83,18.88 | v12.04,35.43 12.95,36.35 16.43,36.35 v16.51,36.27
  Bottom 1.016: 12.72,13.84 VGA_CON.4 | 4.83,18.88 VGA_DB15-F.13
INT  (via drill 0.4, 0.6)
  Top 0.203: U3.78 33.38,39.86 33.63,40.11 35.23,40.11 v35.36,39.98
  Top 0.762: R28.2 47.95,43.59 v47.75,43.79
  Top 1.016: v45.72,48.13 U1.D2 | R28.2 R27.2
  Bottom 0.203: v35.36,39.98 35.71,39.62 44.02,39.62 45.72,41.33 45.72,43.79 | 45.72,43.79 v45.72,48.13 | 45.72,43.79 v47.75,43.79
LINE_OUT_L
  Top 0.203: U3.99 22.88,39.86 22.61,40.13 16.79,40.13 R11.2
LINE_OUT_R
  Top 0.203: U3.98 23.38,39.92 22.76,40.54 17.02,40.54 16.31,41.25 16.31,43.03 R12.2
N$1
  Top 0.254: R2.1 22.55,48.69
  Top 0.762: U1.D10 23.88,50.01 22.55,48.69
N$2
  Top 0.508: SJ1.1 24.69,48.62
  Top 0.762: U1.D9 26.42,50.34 24.69,48.62
N$3
  Top 0.508: R15.1 42.16,9.5 44.65,11.99 46.32,11.99 46.57,12.24
  Top 1.016: 46.57,12.24 PS2_KEYBOARD.1
N$4
  Top 0.508: R19.1 43.87,13.01 43.87,14.07 44.48,14.68
  Top 1.016: 44.48,14.68 PS2_KEYBOARD.5
N$5  (via drill 0.6, 0.6 pad 0.61)
  Top 0.508: v16.61,2.54 5V/3V.2 | v43.33,5.69 R25.1
  Top 1.016: R25.1 R26.1 | PS2_KEYBOARD.4 44.55,5.69 v43.33,5.69
  Bottom 0.508: v16.61,2.54 18.14,1.02 34.19,1.02 38.86,5.69 v43.33,5.69
N$6
  Top 1.016: CD.1 32.48,46.79 R5.1
N$7
  Top 0.203: R27.1 51.08,41.15 51.08,35.08 49.94,33.94
  Top 1.016: UEXT.4 49.94,33.94
N$9
  Top 1.016: R11.1 C19.1 10.54,39.65 9.32,38.43 AUDIO.5
N$10
  Top 1.016: R12.1 C20.1 10.35,45.62 AUDIO.2
N$11
  Top 1.016: CD.3 27.36,43.98 R21.1
N$12
  Top 0.203: R28.1 51.49,42.77 51.49,32.95 49.94,31.4
  Top 1.016: UEXT.6 49.94,31.4
N$29  (via drill 0.6)
  Top 0.254: 13.08,10.9 12.19,11.79 12.19,15.59 11.79,16 | v12.32,19.18 12.7,19.56 12.7,27.15 R16.1
  Top 1.016: 11.79,16 VGA_DB15-F.2 | VGA_CON.2 13.08,10.9 | R16.1 R17.1 R18.1
  Bottom 1.016: VGA_DB15-F.2 12.32,19.01 v12.32,19.18
N$37
  Top 0.254: 13.11,8.33 11.68,9.75 11.68,13.82 11.28,14.22
  Top 1.016: R8.1 R7.1 R6.1 13.18,5.41 13.56,5.79 13.56,7.11 13.97,7.52 VGA_CON.1 13.11,8.33 | 11.28,14.22 VGA_DB15-F.1
N$40
  Top 0.254: 13.08,13.44 12.7,13.82 12.7,17.37 11.07,19 | 11.81,20.79 12.19,21.17 12.19,32.77 R22.1
  Top 1.016: 11.07,19 VGA_DB15-F.3 11.81,20.79 | VGA_CON.3 13.08,13.44 | R22.1 R23.1 R24.2
N$86
  Top 0.508: PS2_KEYBOARD.SHIELD3 48.3,20.45 C21.1
  Top 1.778: PS2_KEYBOARD.SHIELD3 52.07,16.68 52.07,12.04 | 52.07,12.04 PS2_KEYBOARD.SHIELD2 | 52.07,12.04 52.07,12.09 | PS2_KEYBOARD.SHIELD1 52.07,7.4 52.07,12.04
PS2_CLK  (via drill 0.4)
  Top 0.508: R19.2 39.75,10.67 v39.37,10.67 39.32,10.62 39.32,8.61 R26.2
  Top 1.016: R19.2 40.39,13.08 R14.1
  Bottom 0.203: v39.37,10.67 39.37,11.38 43.64,15.65 43.64,21.82 45.21,23.39 45.21,28.37 46.05,29.21 53.39,29.21 54.51,30.33 54.51,48.67 54,49.17 34.65,49.17 33.83,49.99
  Bottom 1.016: 33.83,49.99 U1.D7
PS2_DATA  (via drill 0.4)
  Top 0.203: R15.2 40.39,9.14 | 41.99,7.54 R25.2
  Top 0.254: R15.2 41.27,10.16 41.27,12.34 R13.1 | 40.39,9.14 41.99,7.54
  Top 0.508: R13.1 42.85,13.92 v43,13.92
  Bottom 0.203: v43,13.92 43,14.4 44.04,15.44 44.04,21.67 46.56,24.18 47.14,24.18 47.75,24.79 47.75,25.91 48.51,26.67 51.41,26.67 54.91,30.18 54.91,48.87 54.2,49.58 36.78,49.58 36.37,49.99
  Bottom 1.016: 36.37,49.99 U1.D6
R1
  Top 0.203: R6.2 15.19,5.31 15.19,26.42 16.2,27.43 16.2,29.26 16.61,29.67 18.77,29.67 19.3,30.2 U3.15
R2
  Top 0.203: R7.2 15.8,3.89 15.8,5.79 15.6,5.99 15.6,26.26 16.61,27.28 16.61,29.06 16.82,29.26 18.92,29.26 19.36,29.7 U3.16
R3
  Top 0.203: R8.2 15.8,1.85 15.8,3.25 16.2,3.66 16.2,5.99 16,6.2 16,24.97 16.23,25.2 16.66,25.2 17.22,25.76 18.09,25.76 18.44,26.11 18.44,26.9 19.74,28.2 U3.19
RAM_#CS  (via drill 0.3, 0.4)
  Top 0.254: v37.08,11.3 36.88,11.51 v36.88,14.48 | U3.50 34.38,22.49 35.43,21.44 v35.43,21.29 | v41.15,20.93 41.15,20.62 42.87,18.9 arc45 43,18.85 v44.86,18.85
  Bottom 0.203: U5.19 23.03,8.04 25.55,10.57 35.79,10.57 36.52,11.3 v37.08,11.3 | v35.43,21.29 35.43,21.01 35.92,20.52 37.95,20.52 | 37.95,20.52 40.74,20.52 v41.15,20.93 | 37.95,20.52 37.95,18.29 36.93,17.27 36.93,16.26 37.01,16.17 U2.6 36.88,15.5
  Bottom 0.254: v36.88,14.48 36.88,15.5
  Bottom 0.508: R20.1 v44.86,18.85
SPI_CLK  (via drill 0.3, 0.6)
  Top 0.203: U3.84 30.38,38.05 30.33,38 30.33,37.19 28.6,35.46 24.79,35.46 24.59,35.26 22.3,35.26 v21.74,35.81
  Top 0.508: R10.2 16.46,46.08 v16.76,45.77
  Bottom 0.203: v21.74,35.81 21.74,36.32 19.36,38.71 19.36,43.69 17.27,45.77 v16.76,45.77
SPI_CS  (via drill 0.3, 0.6)
  Top 0.203: U3.88 28.38,38.22 v28.85,37.74 | v24.79,37.85 24.54,38.1 22.12,38.1 21.34,38.89 v21.34,39.17
  Top 1.016: v21.89,44.78 R3.2
  Bottom 0.203: v28.85,37.74 28.19,38.41 25.35,38.41 v24.79,37.85 | v21.34,39.17 20.57,39.93 20.57,44.07 21.29,44.78 v21.89,44.78
SPI_MISO  (via drill 0.3, 0.6)
  Top 0.203: U3.86 29.38,38.13 29.52,38 29.52,37.49 28.3,36.27 25.45,36.27 24.03,37.69 21.97,37.69 21.57,38.1 21.18,38.1 v20.93,38.35
  Top 1.016: v18.49,45.77 R9.2
  Bottom 0.203: v20.93,38.35 20.32,38.35 19.76,38.91 19.76,44.91 18.9,45.77 v18.49,45.77
SPI_MOSI  (via drill 0.3, 0.6)
  Top 0.203: U3.85 29.88,38.24 29.92,38.2 29.92,37.34 28.45,35.87 25.3,35.87 23.88,37.29 21.82,37.29 21.41,37.69 20.68,37.69 20.27,38.1 20.27,39.01 v20.42,39.17
  Top 1.016: v20.52,45.77 R4.2
  Bottom 0.203: v20.42,39.17 20.17,39.42 20.17,45.41 v20.52,45.77
TCK  (via drill 0.4)
  Top 0.254: U3.76 34.38,37.4 v34.7,37.08
  Bottom 0.203: v34.7,37.08 35.2,37.08 36.12,38 44.68,38 49.76,43.08 49.76,44.35 52.35,46.94
  Bottom 1.016: 52.35,46.94 JTAG.2
TDI  (via drill 0.3)
  Top 0.203: U3.2 21.29,36.7 21.51,36.47 22.81,36.47 v23.37,35.92
  Bottom 0.203: v23.37,35.92 23.72,36.27 23.72,38.3 24.64,39.22 44.17,39.22 48.54,43.59 48.54,46.84
  Bottom 1.016: 48.54,46.84 JTAG.5
TDO  (via drill 0.4)
  Top 0.254: U3.75 35.78,37.2 35.15,37.82 v35.15,38.05
  Bottom 0.203: v35.15,38.05 35.51,38.41 44.53,38.41 49.35,43.23 49.35,45.11 51.08,46.84
  Bottom 1.016: 51.08,46.84 JTAG.3
TMS  (via drill 0.3)
  Top 0.203: U3.1 21.35,37.2 21.67,36.88 23.32,36.88 v24.28,35.92
  Bottom 0.203: v24.28,35.92 24.13,36.07 24.13,38.1 24.84,38.81 44.35,38.81 48.95,43.41 48.95,45.97 49.81,46.84
  Bottom 1.016: 49.81,46.84 JTAG.4
UEXT_CLK
  Top 0.203: 17.07,51.61 18.29,52.83 54.05,52.83 55.32,51.56 55.32,30.02 49.48,24.18 47.66,24.18
  Top 1.016: R10.1 16.26,48.84 U1.D13 17.07,51.61 | 47.66,24.18 UEXT.9
UEXT_MISO
  Top 0.203: 19.61,51.61 20.42,52.43 53.9,52.43 54.91,51.41 54.91,30.18 51.41,26.67 47.71,26.67
  Top 1.016: R9.1 18.8,48.95 U1.D12 19.61,51.61 | 47.71,26.67 UEXT.7
UEXT_MOSI
  Top 0.203: 22.15,51.61 22.55,52.02 53.75,52.02 54.51,51.26 54.51,30.33 52.1,27.92 49.96,27.92
  Top 1.016: R4.1 21.34,49.45 U1.D11 22.15,51.61 | 49.96,27.92 UEXT.8
UEXT_SSEL  (via drill 0.6)
  Top 0.203: 24.71,46.66 24.71,46.76 24.71,46.97 SJ1.2
  Top 0.254: SJ1.2 24.64,46.94
  Top 1.016: R3.1 v24.71,45.85 24.71,46.66 | 24.77,46.76 24.71,46.76 22.55,46.76 R2.2
  Bottom 0.203: v24.71,45.85 28.83,45.85 31.14,48.16 31.14,50.7 33.27,52.83 54.05,52.83 55.32,51.56 55.32,30.02 50.68,25.38 50.19,25.38
  Bottom 1.016: 50.19,25.38 UEXT.10
VCC  (via drill 0.3, 0.4, 0.6, 0.6 pad 0.61)
  Top 0.203: v31.65,25.45 31.95,25.15 31.95,24.11 31.88,24.03 U3.45 31.88,22.55 32.36,22.07 32.36,21.49 33.17,20.68 v33.17,20.32 | U3.55 37.04,27.2 37.9,26.34 v37.9,25.76 | U3.67 36.91,33.2 36.93,33.22 38.12,33.22 38.15,33.25 | 36.37,22.35 C8.1 | 43.51,34.54 v43.51,31.11 | C3.1 18.85,24.49
  Top 0.254: U3.22 19.33,26.7 18.87,26.24 18.87,25.83 18.34,25.3 17.75,25.3 v17.5,25.04 | U3.26 22.38,23.88 21.82,23.88 20.98,24.71 20.22,24.71 | 33.17,19.61 v33.17,20.32 | v32.72,17.37 32.72,19.15 33.17,19.61 | v22.05,17.8 22.05,20.55 20.22,22.38 20.22,24.71 | U3.79 32.88,39.97 33.45,40.54 34.39,40.54 C15.1 | U3.96 24.38,40.06 23.44,41 22,41 C18.1 | U3.92 26.38,39.94 25.09,41.22 | 33.17,19.61 34.77,19.61 36.27,21.11 C8.1 | 25.09,41.22 25.07,41.25 | 25.09,41.22 24,42.32 C17.1 | C14.1 38.15,33.25 | U3.11 19.41,32.21 18.97,32.64 17.83,32.64 C1.1 | 20.22,24.71 19.07,24.71 18.85,24.49
  Top 0.508: v39.62,25.76 39.8,25.93 C9.1 | 20.68,43.38 C18.1 | C17.1 23.72,43.28 v23.82,43.38 | 36.83,45.01 36.83,45.36 46.23,45.36 46.86,44.73 | JTAG.1 53.62,45.64 52.7,44.73 46.86,44.73 | 46.86,42.49 U4.3 | 46.86,44.73 46.86,42.49 | C14.1 39.27,34.54 43.51,34.54 46.58,34.54 46.86,34.82 46.86,35.54 | 46.86,42.49 46.86,35.54 | 46.86,35.54 UEXT.1 | 22.81,2.59 U1.3V3 | v17.02,4.95 17.91,4.06 5V/3V.3 22.81,4.06 | v18.44,43.38 20.68,43.38 | 20.68,43.38 v21.39,43.38 | v8.18,25.5 v11.33,25.5 | v35.6,3.96 35.6,2.55 37.13,1.02 51.46,1.02 53.7,3.25 53.7,18.39 50.85,21.23 47.4,21.23 44.04,24.59 v43.66,24.59
  Top 0.762: v36.37,23.62 36.37,22.35 | 36.83,43.76 U4.5 | 36.83,42.49 U4.6 | 36.83,43.76 36.83,42.49 | R5.2 36.83,45.01 36.83,43.76 | SPI_PGM.6 36.83,46.91 36.83,45.36 | C15.1 35.71,41.38 36.83,42.49 | v17.5,25.04 17.5,24.11 | VR1(3.3V).3 22.94,5.18 C10.1 22.81,4.06 22.81,2.59
  Top 1.016: R5.2 32.48,45.01 CD.4 33.23,43.28 v34.09,43.28 | VR1(3.3V).3 26.57,5.18 v27.38,4.37 v30.23,4.37 | C2.1 17.5,24.11 C3.1 | v16.33,32.26 C1.1
  Bottom 0.203: 32.21,26.45 U2.33 | U5.49 33.43,20.07 v33.17,20.32 | U5.43 28.63,18.57 27.64,17.58 | 30.91,28.85 C7.1 | C7.1 30.94,28.85 31.24,29.16 31.24,29.67 32.56,30.99 33.43,30.99 33.73,30.68 43.08,30.68 v43.51,31.11 | C7.1 30.84,28.85 | U2.11 33.01,16.31 32.72,16.61 v32.72,17.37
  Bottom 0.254: v31.65,25.45 31.65,25.88 32.21,26.45 | C25.1 35.71,5.59 35.83,5.7 35.83,6.2 | 35.83,6.2 U5.3 | U5.1 37.43,6.59 37.03,6.2 35.83,6.2 | C22.1 31.04,5.59 31.03,5.6 U5.9 | U5.14 27.03,6.45 26.16,5.59 | U5.27 16.63,6.08 16.71,5.99 17.02,5.99 | 27.64,17.58 22.28,17.58 v22.05,17.8 | U2.33 32.21,27.76 31.5,28.47 31.29,28.47 30.91,28.85
  Bottom 0.508: v37.9,25.76 v39.62,25.76 39.62,24.33 | v36.37,23.62 37.08,24.33 39.62,24.33 | 39.62,24.33 43.08,24.33 43.33,24.59 v43.66,24.59 | v21.39,43.38 21.39,43.08 22.1,42.37 23.82,42.37 | 14.17,25.04 16.71,25.04 | 16.71,25.04 v17.5,25.04 17.5,30.99 | 16.71,25.04 C24.1 | 31.13,4.17 30.43,4.17 v30.23,4.37 | 31.13,4.17 C22.1 | 17.5,30.99 17.5,31.09 v16.33,32.26 | v27.38,4.37 26.16,5.59 C23.1 | 17.02,5.99 C26.1 | v18.44,43.38 18.75,43.08 18.75,38.51 19.46,37.8 19.46,31.67 18.77,30.99 17.5,30.99 | 23.82,42.37 25.86,42.37 26.77,43.28 v34.09,43.28 | 23.82,42.37 v23.82,43.38 | v17.02,4.95 11.66,4.95 11.07,5.54 11.07,9.4 9.09,11.38 7.06,11.38 3.71,14.73 3.71,24.18 5.03,25.5 v8.18,25.5 | 13.72,25.5 VGA_CON.8 | 31.13,4.17 35.61,4.17 | v35.6,3.96 v35.61,3.96 35.61,4.17 | C25.1 35.61,4.17
  Bottom 1.016: VGA_CON.8 14.17,25.04 | v11.33,25.5 13.72,25.5 | v17.02,4.95 17.02,5.99
VCC/2  (via drill 0.3, 0.4, 0.4 pad 0.61, 0.6 pad 0.61)
  Top 0.203: C5.1 28.38,21.89 | v27.61,25.76 28.6,26.75 28.6,28.65 28.19,29.06 26.77,29.06 26.67,28.96 23.72,28.96 v23.47,28.7 | U3.66 37.04,32.7 37.16,32.82 39.19,32.82 C13.1 | U3.17 21.55,29.2 v21.67,29.31
  Top 0.254: U3.17 19.47,29.2 18.82,28.55 v18.34,28.55 | 28.38,21.89 U3.38 | v27.43,21.23 27.96,21.23 C5.1 | U3.81 31.88,39.9 31.65,40.13 31.42,40.13 C16.1
  Top 0.508: C13.1 40.28,33.71 42.19,33.71 42.85,33.05 42.85,32.03 42.52,31.7 42.52,30.63 43.48,29.67 43.48,26.31 47.24,22.55 v48.82,22.55 | C16.1 30.4,41.88 29.92,42.37 v29.52,42.37 | R1.1 22.4,8.05 v22.4,6.17 | v20.47,6.17 18.24,8.41 v18.24,20.52
  Top 0.762: v18.34,28.55 17.55,28.55 C4.1
  Top 1.016: R1.1 24.08,8.13 VR1(3.3V).2 VR1(3.3V).4 30.91,8.03 C12.1 37.19,8.03 C11.+ 38.56,7.21 v39.09,7.21
  Bottom 0.203: v27.43,21.23 26.36,22.3 26.36,24.84 27.28,25.76 v27.61,25.76 | v23.47,28.7 22.86,29.31 v21.67,29.31
  Bottom 0.508: v29.52,42.37 26.98,42.37 22.55,37.95 22.55,33.78 18.47,29.69 18.47,28.55 | 18.47,28.55 18.47,20.75 v18.24,20.52 | v20.47,6.17 v22.4,6.17 | 18.47,28.55 v18.34,28.55 | v39.09,7.21 48.21,7.21 49.23,8.23 52.78,8.23 55.02,10.46 55.02,16.97 49.43,22.55 v48.82,22.55
VSYNC  (via drill 0.4)
  Top 0.254: U3.3 19.68,36.2 19.43,36.45 17.86,36.45 v17.27,37.03 | 6.15,22.49 6.5,22.84 6.5,25.86 11.12,30.48 11.12,35.56 v12.01,36.45
  Top 1.016: VGA_DB15-F.14 6.15,22.49
  Bottom 0.254: 12.47,16.13 10.03,16.13 8.89,17.27 7.49,17.27 6.73,18.03 6.73,20.55 6.35,20.93 | v12.01,36.45 12.6,37.03 v17.27,37.03
  Bottom 1.016: 12.47,16.13 VGA_CON.5 | 6.35,20.93 VGA_DB15-F.14
XA0  (via drill 0.3)
  Top 0.203: U3.52 37.04,25.7 38.86,23.88 38.86,20.07 39.67,19.25 39.67,17.63 40.36,16.94 v40.54,16.94
  Bottom 0.203: U5.23 19.83,9.92 20.88,10.97 35.64,10.97 37.26,12.6 38.63,12.6 41.01,14.98 U2.1 41.01,16.47 v40.54,16.94
XA1  (via drill 0.3)
  Top 0.203: U3.56 37.1,27.7 38.56,26.24 38.56,24.84 39.27,24.13 39.27,20.22 40.08,19.41 40.08,18.19 v40.41,17.86
  Bottom 0.203: U5.24 19.03,9.73 20.68,11.38 35.48,11.38 37.11,13.01 38.25,13.01 40.21,14.97 U2.2 40.21,16.33 39.88,16.66 39.88,17.32 v40.41,17.86
XA2  (via drill 0.3)
  Top 0.203: U3.57 37.16,28.2 38.96,26.39 38.96,24.99 39.67,24.28 39.67,20.37 40.74,19.3 v40.74,18.75
  Bottom 0.203: U5.25 18.23,9.54 20.47,11.79 35.33,11.79 36.96,13.41 37.85,13.41 39.41,14.98 U2.3 39.41,17.77 40.39,18.75 v40.74,18.75
XA3  (via drill 0.3)
  Top 0.203: U3.61 38.05,30.2 38.53,30.68 39.98,30.68 41.6,29.06 41.6,23.24 v41.15,22.78
  Bottom 0.203: U5.26 17.43,9.35 20.27,12.19 35.18,12.19 36.8,13.82 37.44,13.82 38.61,14.99 U2.4 38.61,17.53 40.79,19.71 41.4,19.71 42.22,20.52 42.22,21.36 41.81,21.77 41.81,22.12 v41.15,22.78
XA4  (via drill 0.3)
  Top 0.203: v37.69,16.82 37.16,16.82 36.5,16.15 36.12,16.15 34.29,14.33 27.41,14.33 v25.93,12.85 | U3.62 37.99,30.7 38.38,31.09 40.13,31.09 42.01,29.21 42.01,22.73 v41.15,21.87
  Bottom 0.203: v25.93,12.85 25.88,12.9 23.01,12.9 17.43,18.49 U5.29 | v41.15,21.87 41.81,21.21 41.81,20.68 41.25,20.12 40.64,20.12 37.81,17.29 37.81,16.82 | 37.81,16.82 U2.5 | v37.69,16.82 37.81,16.82
XA5  (via drill 0.3)
  Top 0.203: v26.85,12.85 26.85,13.08 27.69,13.92 34.44,13.92 36.27,15.75 36.68,15.75 37.08,16.15 40.66,16.15 41.35,16.84 v41.35,17.32 | U3.65 37.1,32.2 37.31,32.41 38.12,32.41 38.63,31.9 40.44,31.9 42.82,29.52 42.82,22.94 v43.08,22.68
  Bottom 0.203: U2.18 27.41,14.08 26.85,13.51 | 26.85,13.51 25.68,13.51 25.48,13.31 23.22,13.31 18.23,18.3 U5.30 | 26.85,13.51 v26.85,12.85 | v41.35,17.32 41.58,17.32 43.23,18.97 43.23,22.53 v43.08,22.68
XA6  (via drill 0.3)
  Top 0.203: U3.70 30.07,34.7 29.21,33.83 26.52,33.83 25.3,32.61 v25.3,32.26
  Bottom 0.203: U2.19 26.61,15.01 25.32,13.72 23.42,13.72 19.03,18.11 U5.31 19.02,29.44 22.1,32.51 25.04,32.51 v25.3,32.26
XA7  (via drill 0.3)
  Top 0.203: v24.49,31.85 24.49,32.36 26.36,34.24 29.06,34.24 30.02,35.2 U3.71
  Bottom 0.203: U2.20 25.81,14.97 24.97,14.12 23.62,14.12 19.83,17.92 U5.32 19.83,20.51 19.43,20.9 19.43,29.23 22.3,32.11 24.23,32.11 v24.49,31.85
XA8  (via drill 0.3)
  Top 0.203: v23.67,31.45 23.67,32.16 26.16,34.65 28.91,34.65 29.96,35.7 U3.72
  Bottom 0.203: U2.21 25.01,14.95 24.59,14.53 23.82,14.53 20.63,17.73 U5.33 20.63,20.27 19.84,21.06 19.84,29.03 22.5,31.7 23.42,31.7 v23.67,31.45
XA9  (via drill 0.3)
  Top 0.203: v22.86,31.04 22.86,31.9 26.01,35.05 28.75,35.05 29.9,36.2 U3.73
  Bottom 0.203: U2.22 23.28,15.63 21.29,17.63 21.29,18.29 21.43,18.43 U5.34 21.43,20.03 20.24,21.21 20.24,28.83 22.45,31.04 v22.86,31.04
XA10  (via drill 0.3)
  Top 0.203: v20.52,8.69 20.37,8.69 19.76,9.3 19.76,9.86 22.71,12.8 22.71,20.5 20.9,22.3 v20.9,23.82 | v24.89,30.02 25.15,30.28 25.81,30.28 28.55,33.02 29.57,33.02 30.38,33.83 32.89,33.83 v33.15,33.58
  Top 0.254: v33.76,36.88 33.88,37 U3.77
  Bottom 0.203: U5.22 20.63,8.58 v20.52,8.69 | v20.9,23.82 21.26,23.82 23.75,26.31 24.21,26.31 U2.23 24.21,27.72 25.15,28.65 25.15,29.77 v24.89,30.02
  Bottom 0.254: v33.15,33.58 33.15,33.78 33.76,34.39 v33.76,36.88
XA11  (via drill 0.3)
  Top 0.203: v25.3,31.34 27.03,33.07 v27.03,33.17 | U3.90 27.38,38.1 v27.03,37.74
  Bottom 0.203: U5.35 22.23,19.79 20.75,21.26 20.75,22.76 23.9,25.91 24.46,25.91 25.01,26.46 U2.24 25.01,27.81 25.55,28.35 25.55,31.09 v25.3,31.34 | v27.03,33.17 27.28,33.43 27.28,37.49 v27.03,37.74
XA12  (via drill 0.3)
  Top 0.203: U3.93 25.88,37.98 v26.11,37.74
  Bottom 0.203: U5.36 23.03,19.62 21.16,21.49 21.16,22.61 24.05,25.5 24.84,25.5 25.81,26.47 U2.25 25.81,27.59 25.96,27.74 25.96,37.59 v26.11,37.74
XA13  (via drill 0.3)
  Top 0.203: v20.47,9.6 20.47,9.96 23.11,12.6 23.11,20.65 22.61,21.16 22.61,22.02 v22.63,22.05 | U3.94 25.38,38.37 25.45,38.3 25.45,37.49 26.01,36.93 v26.62,36.93
  Bottom 0.203: U5.20 22.23,9.93 21.59,10.57 21.08,10.57 20.47,9.96 v20.47,9.6 | v22.63,22.05 22.63,22.4 23.7,23.47 24.43,23.47 25.55,24.59 25.55,25.22 26.61,26.28 U2.26 26.61,27.74 26.36,27.99 26.36,36.68 v26.62,36.93
XA14  (via drill 0.3)
  Top 0.203: v21.34,9.91 21.34,10.21 23.52,12.39 23.52,21.16 v23.27,21.41 | v23.42,27.38 24.28,28.25 26.87,28.25 v27.03,28.4 | U3.25 21.46,25.2 v21.59,25.07
  Bottom 0.203: U5.21 21.43,9.82 v21.34,9.91 | v23.27,21.41 23.37,21.51 23.37,22.58 23.85,23.06 24.59,23.06 25.96,24.43 25.96,25.02 27.41,26.47 U2.27 27.41,28.01 v27.03,28.4 | v21.59,25.07 21.95,25.07 23.42,26.54 v23.42,27.38
XA15/SDRAM_CLK  (via drill 0.3)
  Top 0.203: v24.89,24.84 27.94,27.89 v27.94,28.4 | U3.89 27.88,37.8 v27.94,37.74
  Top 0.254: v27.36,30.12 28.3,30.12 28.75,29.67 32.77,29.67 v33.02,29.92
  Bottom 0.203: U5.38 24.63,19.65 23.55,20.73 23.04,20.73 21.97,21.79 21.97,22.3 23.55,23.88 24.26,23.88 24.89,24.51 v24.89,24.84 | v27.94,37.74 27.69,37.49 27.69,32.92 27.36,32.59 v27.36,30.12 | U2.42 39.41,28.4 37.95,29.87 33.07,29.87 v33.02,29.92
  Bottom 0.254: v27.94,28.4 27.94,28.5 27.36,29.08 v27.36,30.12
XA16/#RAS  (via drill 0.3)
  Top 0.203: U3.59 38.16,29.2 38.56,29.59 v39.22,29.59 | v42.01,15.95 42.42,16.36 42.42,18.19 40.08,20.52 40.08,24.79 v40.44,25.15
  Bottom 0.203: U5.18 23.83,8.26 25.73,10.16 37.01,10.16 42.01,15.16 v42.01,15.95 | v40.44,25.15 40.28,25.3 40.28,26.42 40.21,26.49 U2.43 40.21,27.71 39.83,28.09 39.83,28.98 v39.22,29.59
XA17/#CAS  (via drill 0.3)
  Top 0.203: U3.60 38.1,29.7 38.68,30.28 39.47,30.28 v40.16,29.59 | v42.98,15.9 42.82,16.05 42.82,18.34 40.49,20.68 40.49,24.28 41.1,24.89 41.1,25.76 v40.95,25.91
  Bottom 0.203: U5.17 24.63,8.45 25.93,9.75 37.16,9.75 42.98,15.57 v42.98,15.9 | v40.95,25.91 41.01,25.98 U2.44 41.01,27.72 40.23,28.5 40.23,29.52 v40.16,29.59
XD0  (via drill 0.3, 0.4)
  Top 0.203: v36.22,16.82 34.14,14.73 27.61,14.73 23.93,18.41 23.93,21.74 23.38,22.29 U3.28
  Top 0.254: v38.38,9.96 37.34,9.96 36.25,11.05 36.25,13.87 v36.09,14.02
  Bottom 0.203: U2.7 v36.21,16.81 v36.22,16.82 | U5.2 36.63,8.63 37.95,9.96 v38.38,9.96
  Bottom 0.254: U2.7 36.09,15.51 v36.09,14.02
XD1  (via drill 0.3)
  Top 0.203: v35.31,16.82 33.63,15.14 27.76,15.14 24.33,18.57 24.33,21.92 23.88,22.37 U3.29
  Top 0.254: v35.38,9.09 35.43,9.14 v35.43,13.41
  Bottom 0.203: U5.4 35.03,8.74 v35.38,9.09 | U2.8 35.41,16.71 v35.31,16.82
  Bottom 0.254: U2.8 35.31,15.52 35.31,13.54 v35.43,13.41
XD2  (via drill 0.3)
  Top 0.203: v34.39,16.89 33.05,15.54 27.91,15.54 24.74,18.72 24.74,22.07 24.38,22.43 U3.30
  Top 0.254: v34.47,9.09 34.47,12.34 34.72,12.6 v34.72,12.85
  Bottom 0.203: U5.5 34.23,8.85 v34.47,9.09 | U2.9 34.61,16.67 v34.39,16.89
  Bottom 0.254: v34.72,12.85 34.72,14.86 34.61,14.97 U2.9
XD3  (via drill 0.3)
  Top 0.203: v33.48,16.89 32.54,15.95 28.07,15.95 25.15,18.87 25.15,22.23 24.88,22.49 U3.31
  Top 0.254: v33.55,9.09 33.55,12.6 v33.81,12.85
  Bottom 0.203: U5.7 32.63,8.12 33.55,9.04 v33.55,9.09 | U2.10 33.81,16.12 33.68,16.26 33.68,16.69 v33.48,16.89 | v33.81,12.85 v33.81,12.86
  Bottom 0.254: v33.81,12.86 U2.10
XD4  (via drill 0.3)
  Top 0.203: v31.39,16.82 30.94,16.36 28.22,16.36 25.55,19.02 25.55,22.38 25.38,22.55 U3.32
  Top 0.254: v32.64,9.09 32.64,9.22 31.42,10.44 v31.42,12.85
  Bottom 0.203: U5.8 31.83,8.53 32.38,9.09 v32.64,9.09 | v31.42,12.85 v31.41,12.86 | U2.13 31.41,16.8 v31.39,16.82
  Bottom 0.254: v31.41,12.86 U2.13
XD5  (via drill 0.3)
  Top 0.203: v30.48,17.02 30.23,16.76 28.37,16.76 25.96,19.18 25.96,22.55 25.88,22.63 U3.33
  Top 0.254: v29.26,9.09 29.26,9.45 30.5,10.69 v30.5,12.85
  Bottom 0.203: v30.5,12.85 30.61,12.96 | U5.10 30.23,8.13 v29.26,9.09 | U2.14 30.61,16.89 v30.48,17.02
  Bottom 0.254: 30.61,12.96 U2.14
XD6  (via drill 0.3)
  Top 0.203: v29.62,17.42 29.36,17.17 28.52,17.17 26.36,19.33 26.36,22.66 26.38,22.67 U3.34
  Top 0.254: v28.3,9.09 28.3,9.45 29.59,10.74 v29.59,12.85
  Bottom 0.203: U5.11 29.43,8.01 28.93,8.51 28.88,8.51 v28.3,9.09 | 29.72,15.04 29.81,15.13 | v29.59,12.85 29.72,12.98 | U2.15 29.81,17.23 v29.62,17.42
  Bottom 0.254: 29.81,15.13 U2.15 | 29.72,12.98 29.72,15.04
XD7  (via drill 0.3)
  Top 0.203: v28.8,17.83 28.42,17.83 26.77,19.48 26.77,22.38 26.82,22.43 26.82,22.71 26.88,22.77 U3.35
  Top 0.254: v27.38,9.09 27.38,9.45 28.68,10.74 v28.68,12.85
  Bottom 0.203: v28.68,12.85 28.68,14.63 29.01,14.97 U2.16 29.01,16.15 28.91,16.26 28.91,17.73 v28.8,17.83 | U5.13 27.83,8.29 27.38,8.74 v27.38,9.09
XD8  (via drill 0.3)
  Top 0.203: U3.36 27.38,24.05 27.03,24.41 v27.03,24.56
  Top 0.254: U3.36 27.38,22.2 v27.43,22.15
  Bottom 0.203: U2.29 29.01,26.24 27.86,25.09 27.66,25.09 27.13,24.56 v27.03,24.56 | U5.42 27.83,19.65 28.09,19.91 28.09,21.49 v27.43,22.15
XD9  (via drill 0.3)
  Top 0.254: U3.37 27.88,24.4 v27.91,24.43
  Bottom 0.203: U2.30 29.81,26.33 v27.91,24.43 28.8,23.55 28.8,20.34 29.43,19.72 U5.44
XD10  (via drill 0.3)
  Top 0.203: U3.40 29.38,22.6 29.31,22.53 29.31,21.72 30.33,20.7 v30.33,20.22
  Top 0.254: U3.40 29.38,24.24 v29.06,24.56
  Bottom 0.203: U2.31 30.61,26.45 30.18,26.01 30.05,26.01 29.06,25.02 v29.06,24.56 | 30.23,20.12 v30.33,20.22
  Bottom 0.254: U5.45 30.23,20.12
XD11  (via drill 0.3)
  Top 0.203: U3.41 29.88,22.54 29.72,22.38 29.72,21.87 31.22,20.37 v31.24,20.37 | 29.88,24.94 v29.9,24.94
  Top 0.254: U3.41 29.88,24.94
  Bottom 0.203: U2.32 31.41,26.46 v29.9,24.94 | U5.47 31.83,19.79 v31.24,20.37
XD12  (via drill 0.3)
  Top 0.203: v32.23,20.37 32.18,20.37 31.04,21.51 31.04,22.38 30.88,22.54 U3.43 30.88,24.06 30.58,24.36 30.58,25.35 31.34,26.11 32.46,26.11 33.73,27.38 v33.73,28.3
  Bottom 0.203: U2.35 33.78,27.06 | U5.48 32.63,19.88 32.23,20.27 v32.23,20.37
  Bottom 0.254: U2.35 33.81,28.21 v33.73,28.3
XD13  (via drill 0.3)
  Top 0.203: U3.44 31.38,22.62 31.45,22.55 31.45,22.05 v31.7,21.79
  Top 0.254: U3.44 31.38,24.5 v31.27,24.61
  Bottom 0.203: v31.7,21.79 32.46,21.03 33.4,21.03 33.88,20.55 33.88,20.02 34.23,19.67 U5.50
  Bottom 0.254: U2.36 34.61,26.31 34.24,25.93 33.17,25.93 31.85,24.61 v31.27,24.61
XD14  (via drill 0.3, 0.4)
  Top 0.203: U3.48 33.38,22.32 33.68,22.02 33.68,20.75 34.09,20.34 v34.54,20.34
  Top 0.254: U3.48 33.38,24.53 v33.25,24.66
  Bottom 0.254: U2.37 35.41,26.45 34.44,25.48 34.06,25.48 v33.25,24.66 | U5.51 35.03,19.86 v34.54,20.34
XD15  (via drill 0.3, 0.4)
  Top 0.203: U3.49 33.88,22.38 34.34,21.92 v34.34,21.23
  Top 0.254: U3.49 33.88,24.28 34.14,24.54 34.49,24.54 v34.75,24.79
  Bottom 0.203: v34.34,21.23 34.57,21.23 35.69,20.12 36.42,20.12 36.63,19.91 U5.53
  Bottom 0.254: v34.75,24.79 36.21,26.26 U2.38
XOE  (via drill 0.3)
  Top 0.203: U3.20 20.48,27.74 22.75,27.74 | v24.03,24.56 23.32,25.27 23.32,26.57 22.75,27.14 22.75,27.74 | 22.75,27.74 22.75,28.89 23.22,29.36 26.52,29.36 26.62,29.46 28.35,29.46 28.6,29.21 v33.73,29.21
  Bottom 0.203: U5.37 23.83,19.81 23.32,20.32 22.89,20.32 21.57,21.64 21.57,22.45 23.67,24.56 v24.03,24.56 | U2.41 38.61,28.59 37.74,29.46 33.98,29.46 v33.73,29.21
XWE  (via drill 0.3)
  Top 0.203: v27.76,12.85 27.76,13.11 28.17,13.51 34.59,13.51 36.42,15.34 36.83,15.34 37.24,15.75 40.84,15.75 42.01,16.92 42.01,17.68 v41.48,18.21 | U3.64 37.16,31.7 37.47,32 37.97,32 38.48,31.5 40.28,31.5 42.42,29.36 42.42,22.07 v42.57,21.92
  Top 0.254: v26.47,9.09 26.47,9.35 27.76,10.64 v27.76,12.85
  Bottom 0.203: U2.17 28.21,14.98 28.07,14.83 28.07,13.16 v27.76,12.85 | U5.16 25.43,8.38 26.14,9.09 v26.47,9.09 | v41.48,18.21 41.78,18.21 42.82,19.25 42.82,21.67 v42.57,21.92

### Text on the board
tNames: AREF | GND | D13 | D12 | D11 | D10 | D9 | D8 | D7 | D6 | D5 | D4 | D3 | D2 | D1 | D0 | PS2 | KEYBOARD | MOD-VGA | Rev.B | WWW.OLIMEX.COM/DEV | Made in Bulgaria, 2012 | + | RST | 3V3 | 5V | VIN | A0 | A1 | A2 | A3 | A4 | GND | GND | A5
bStop: WWW.OLIMEX.COM/DEV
